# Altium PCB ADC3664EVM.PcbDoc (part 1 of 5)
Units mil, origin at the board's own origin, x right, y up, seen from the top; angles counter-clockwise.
Board outline 3900 x 2716.54 mil, 10 copper layers (Top Layer, L2 GND, L3 PWR, L4 GND, L5 SIG, L6 GND, L7 GND, L8 PWR, L9 GND, Bottom Layer), stack 61.2 mil thick; 332 components, 223 nets, 1425 pads, 969 vias.
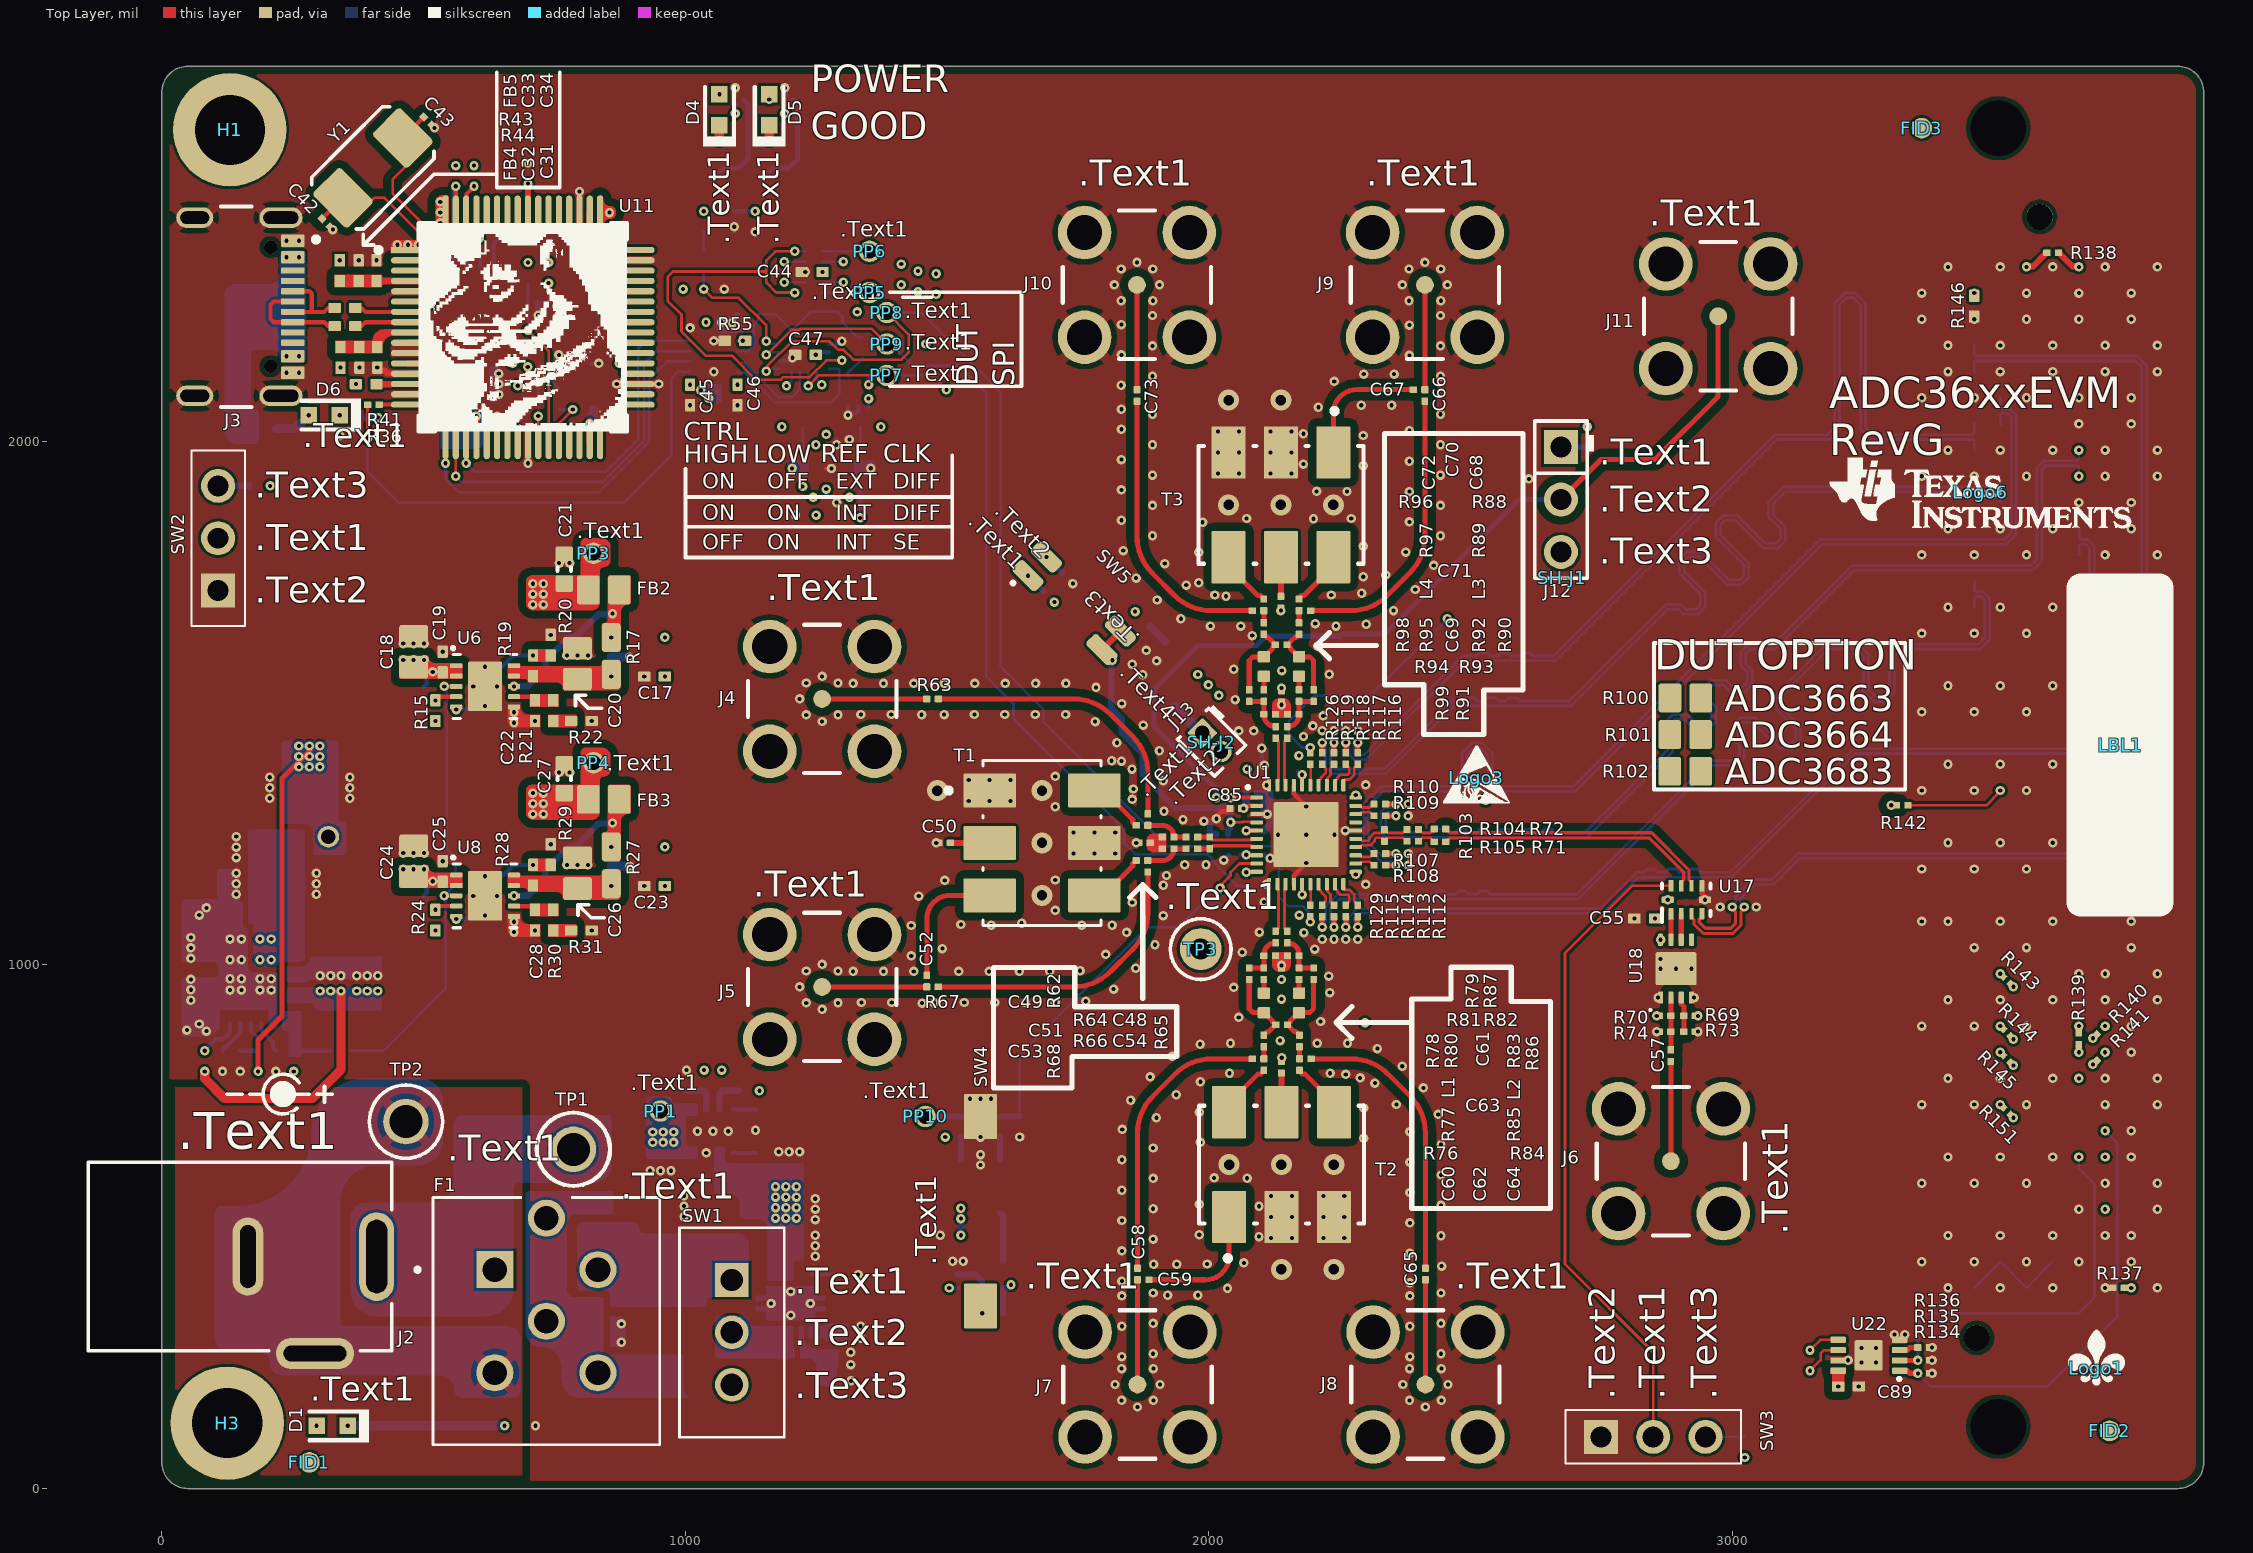
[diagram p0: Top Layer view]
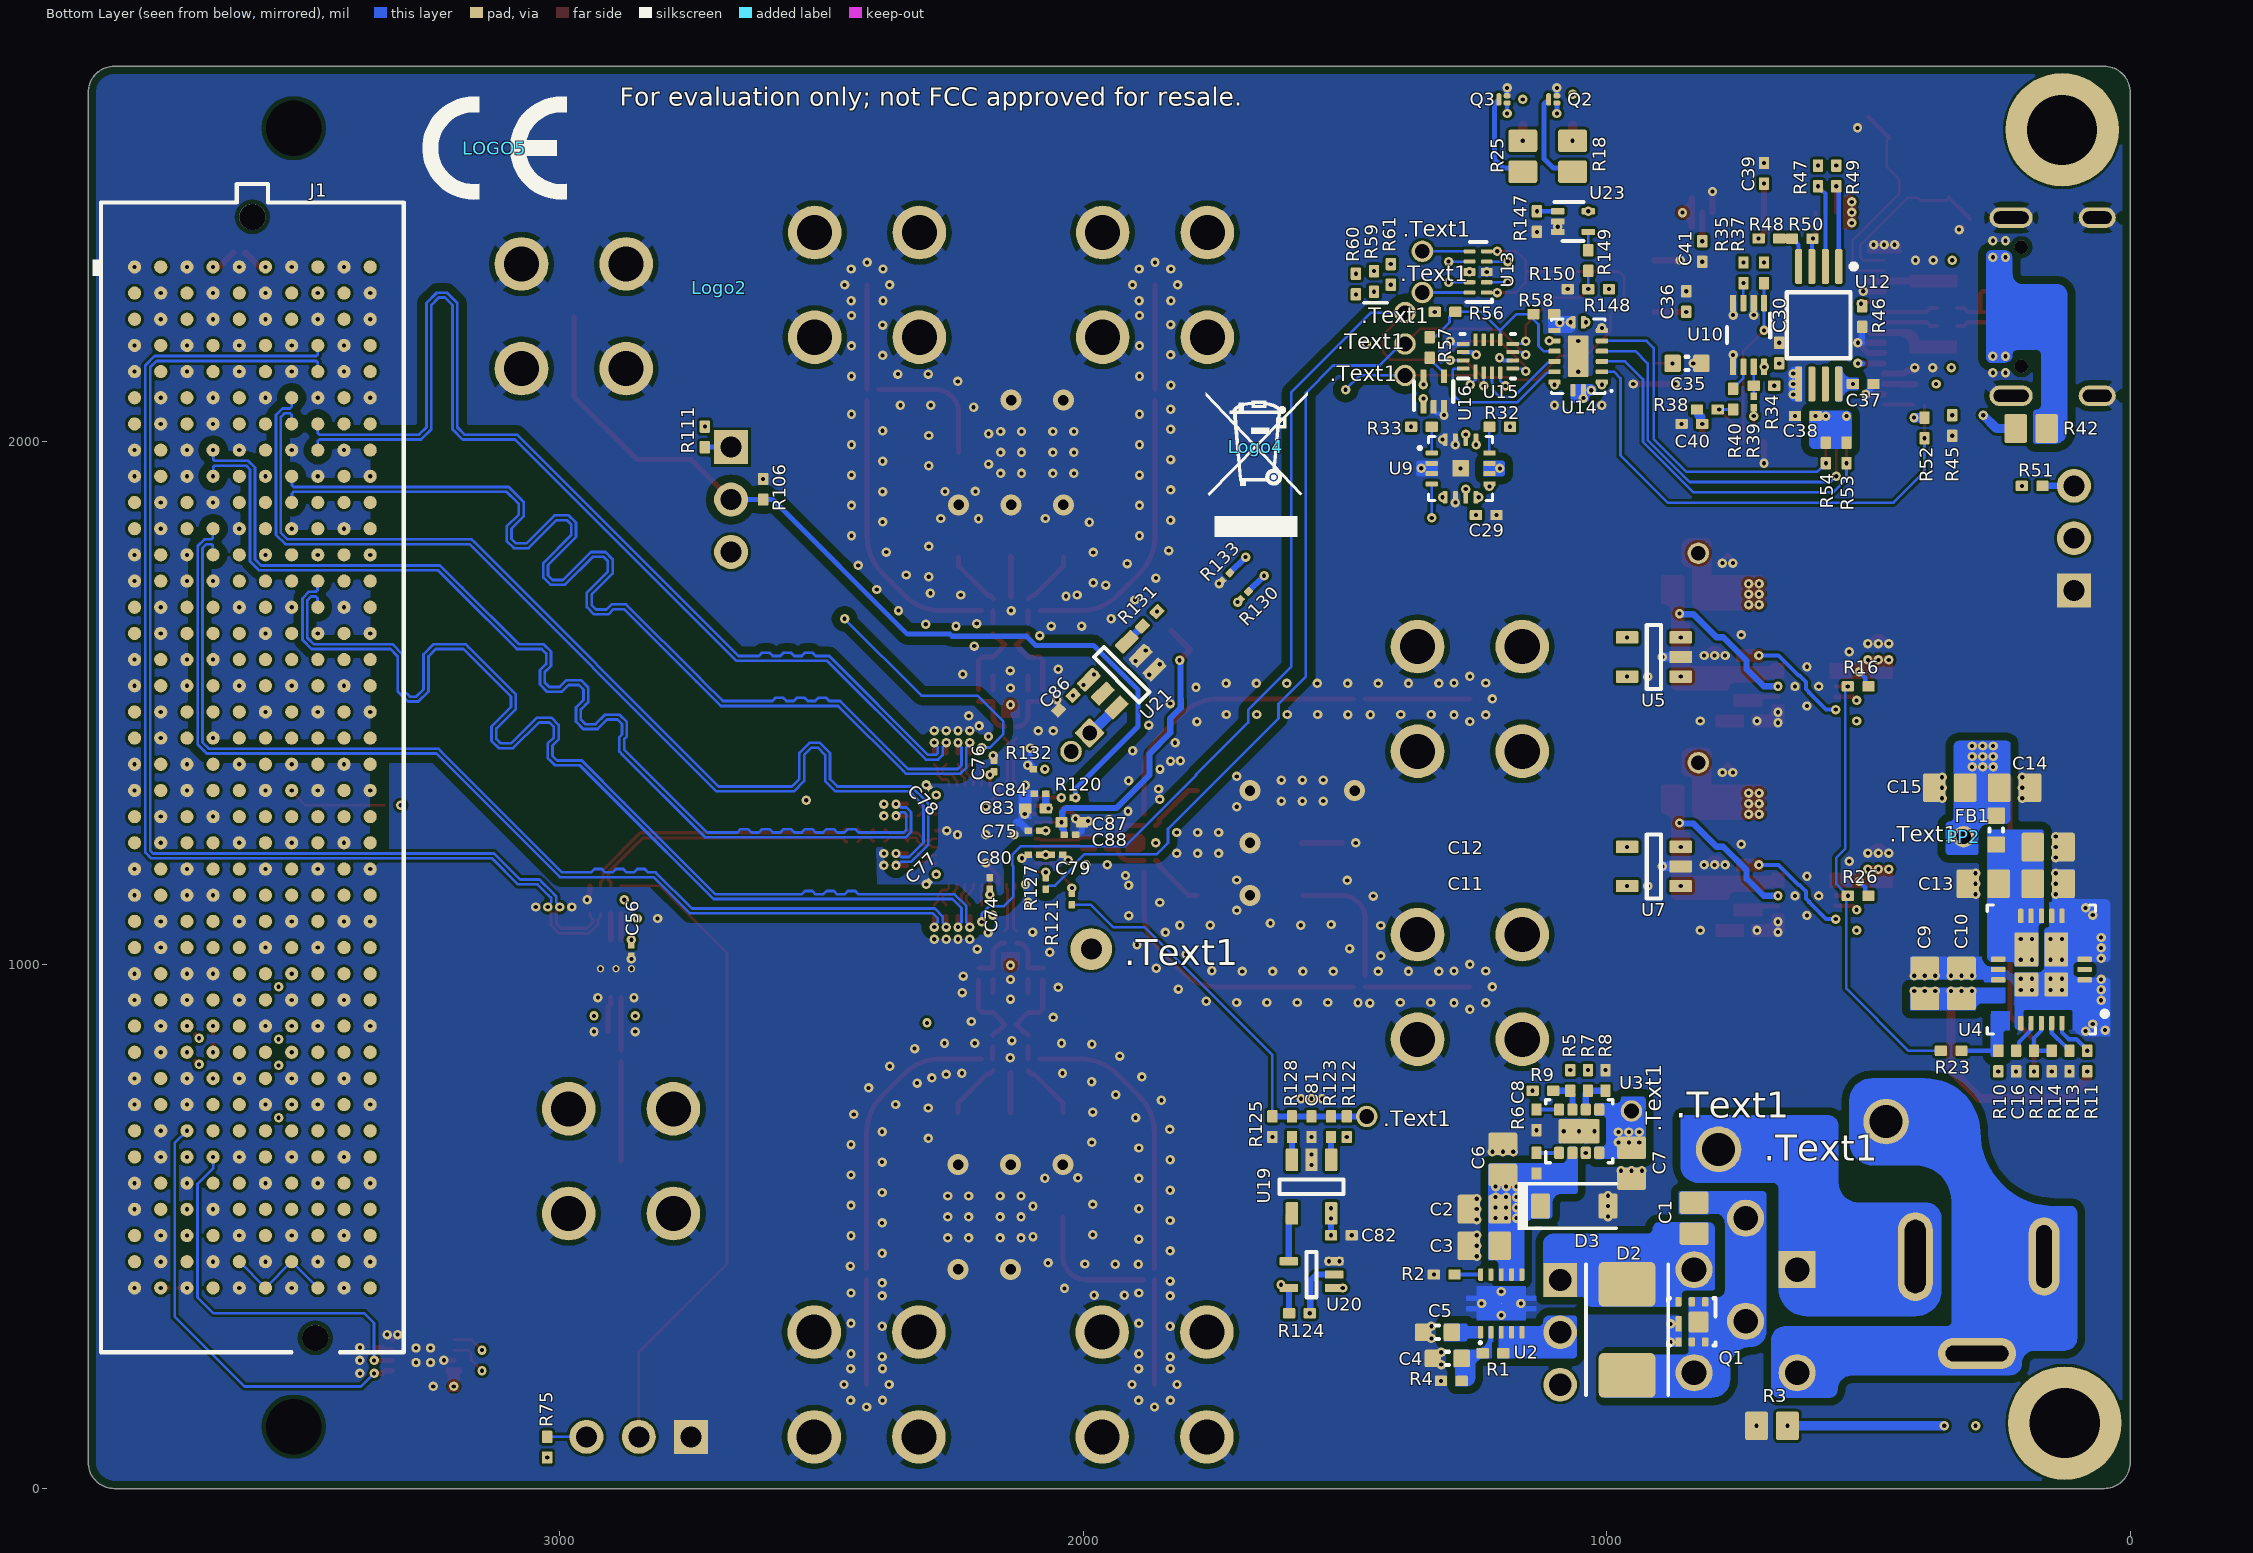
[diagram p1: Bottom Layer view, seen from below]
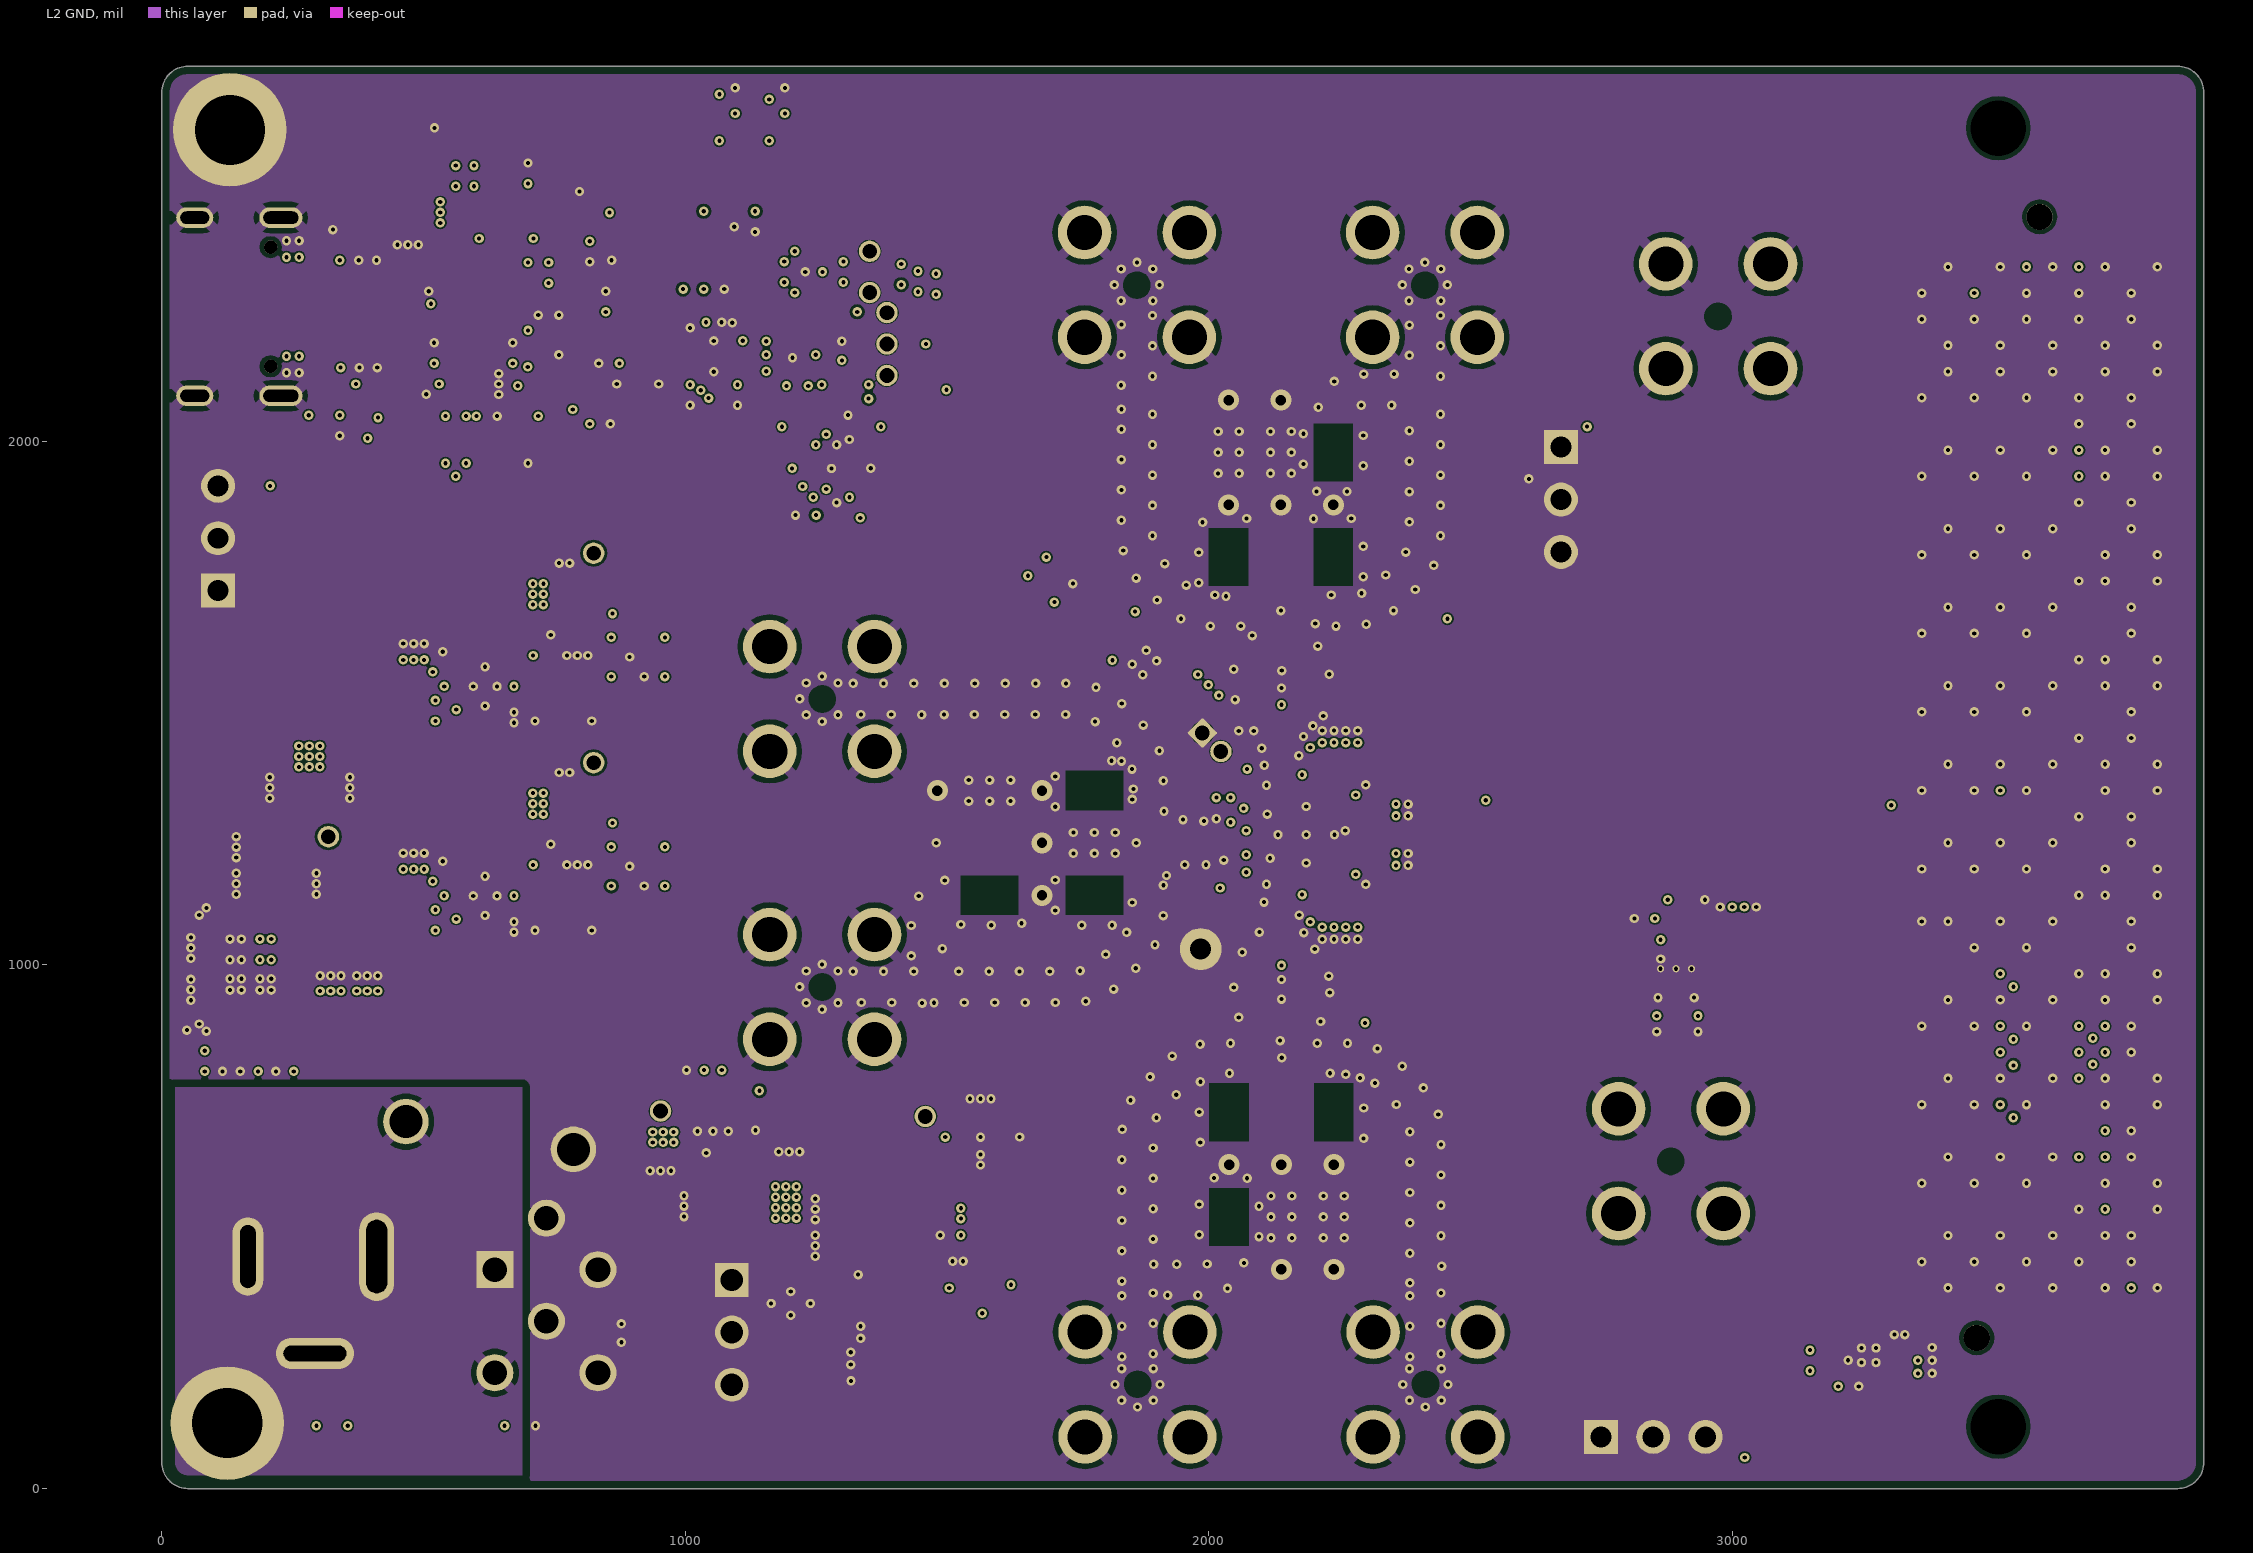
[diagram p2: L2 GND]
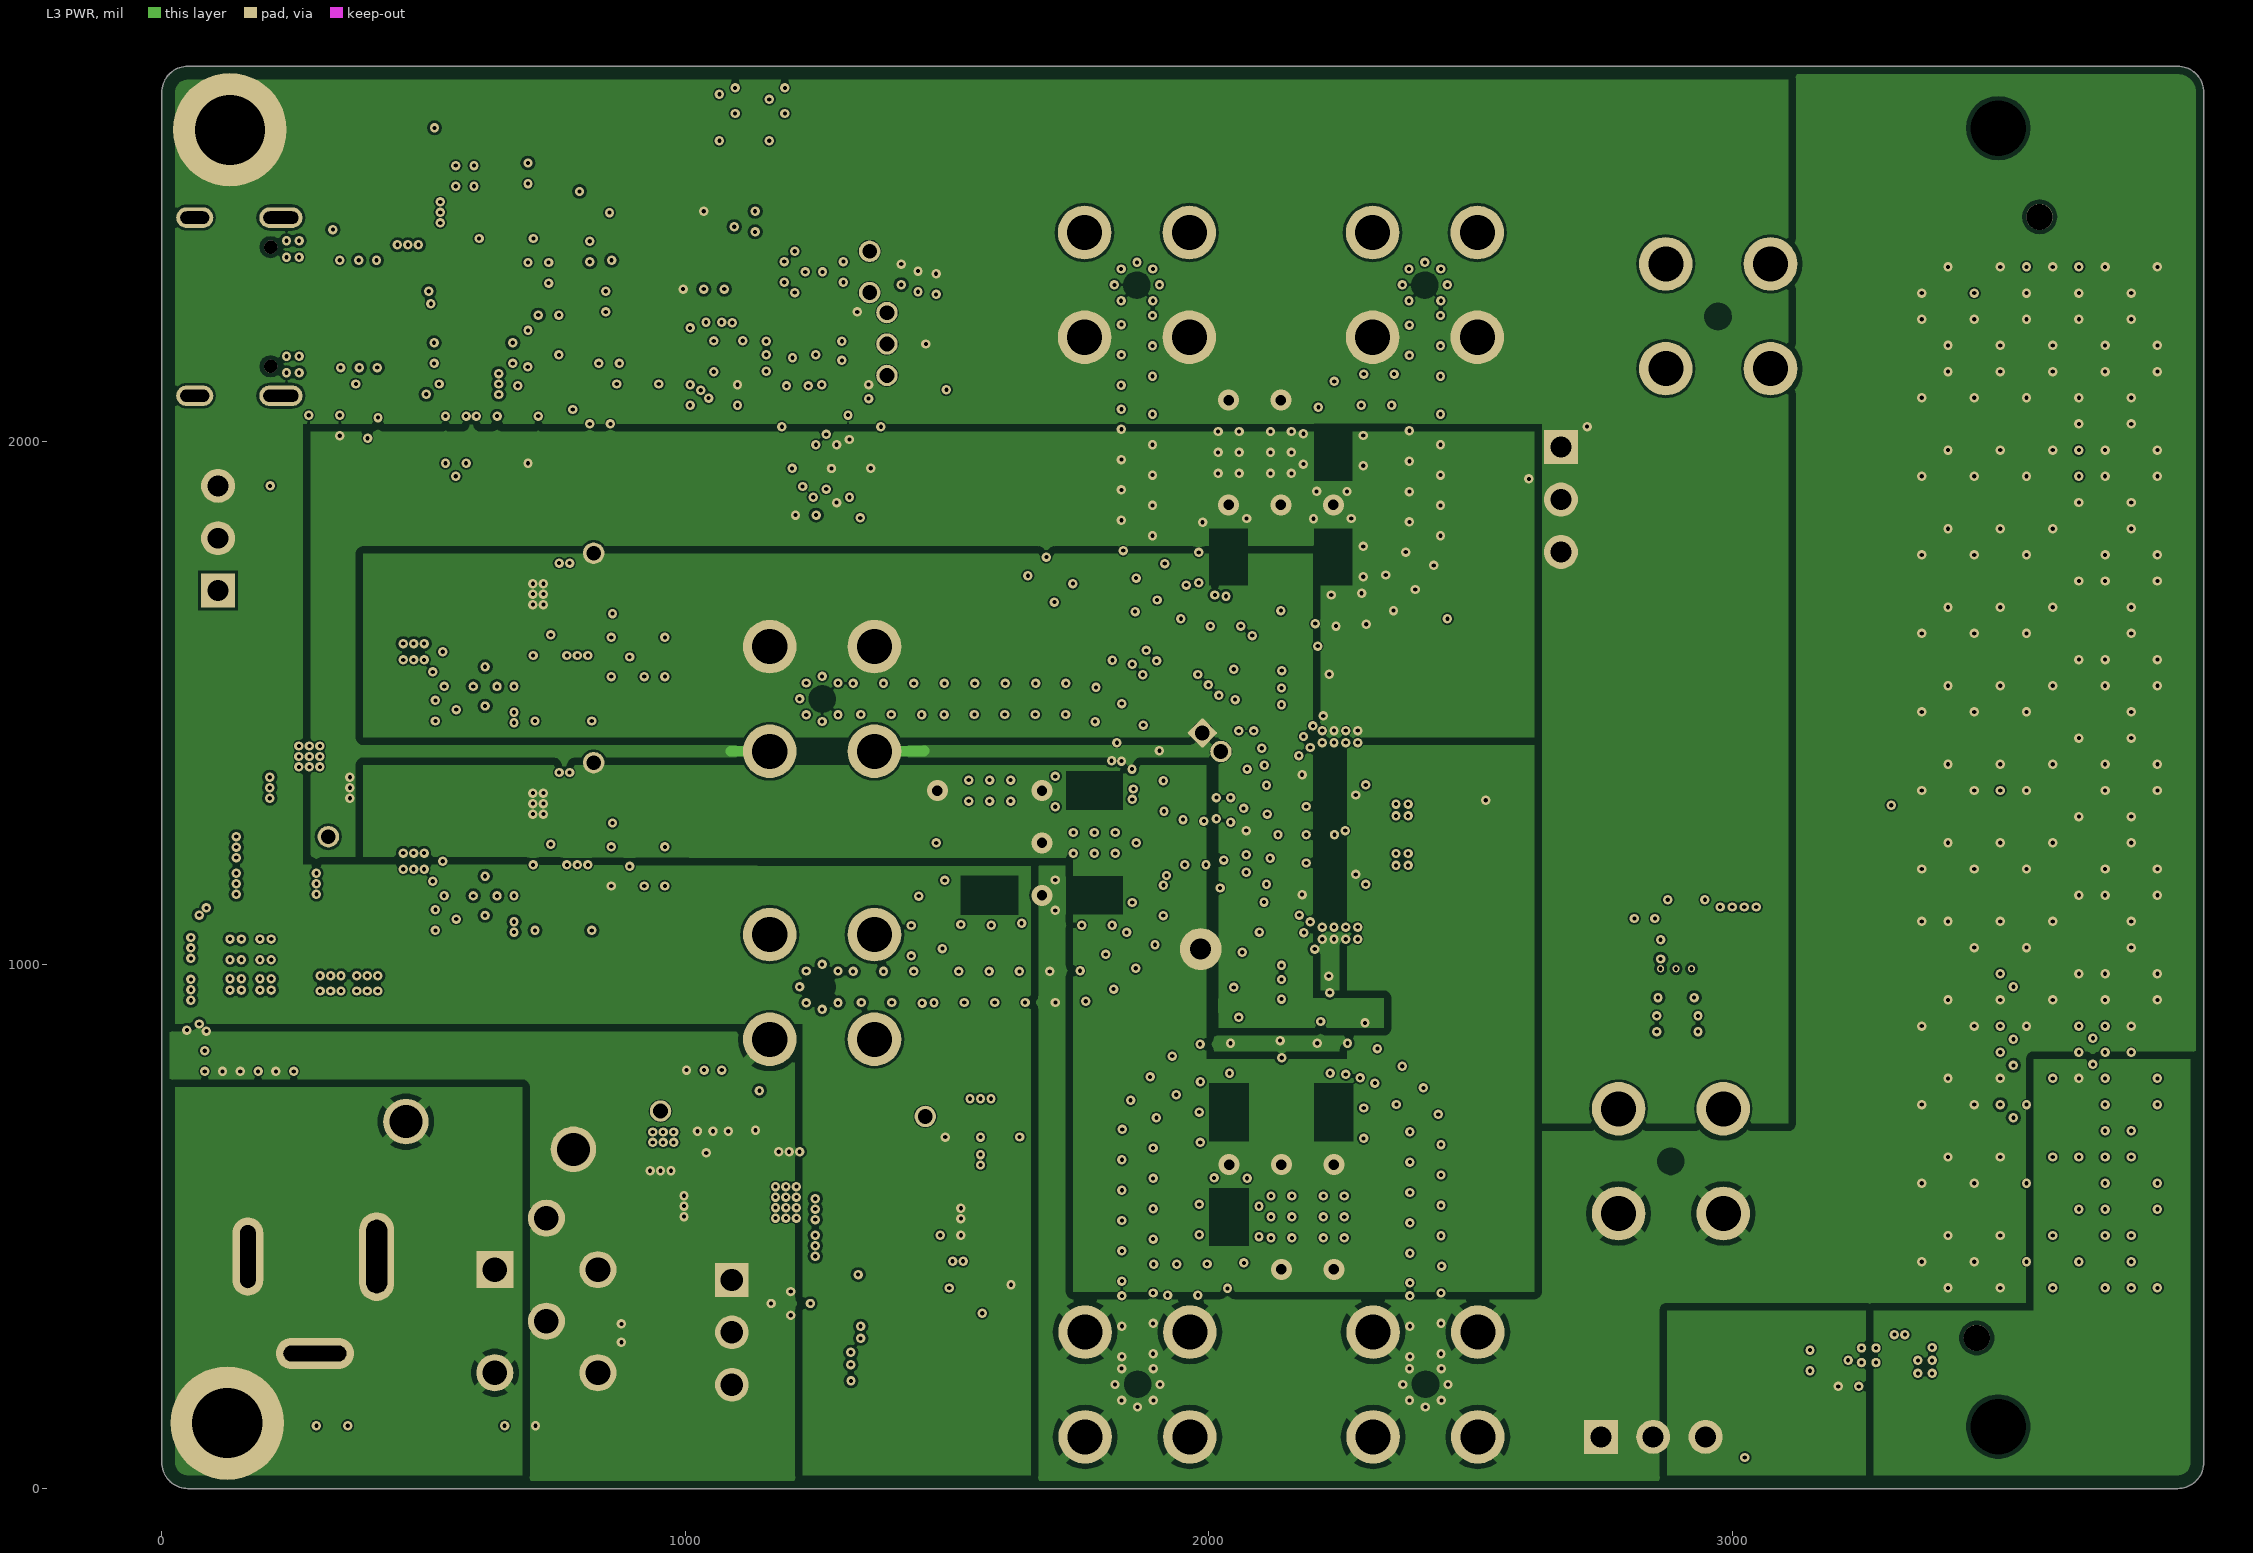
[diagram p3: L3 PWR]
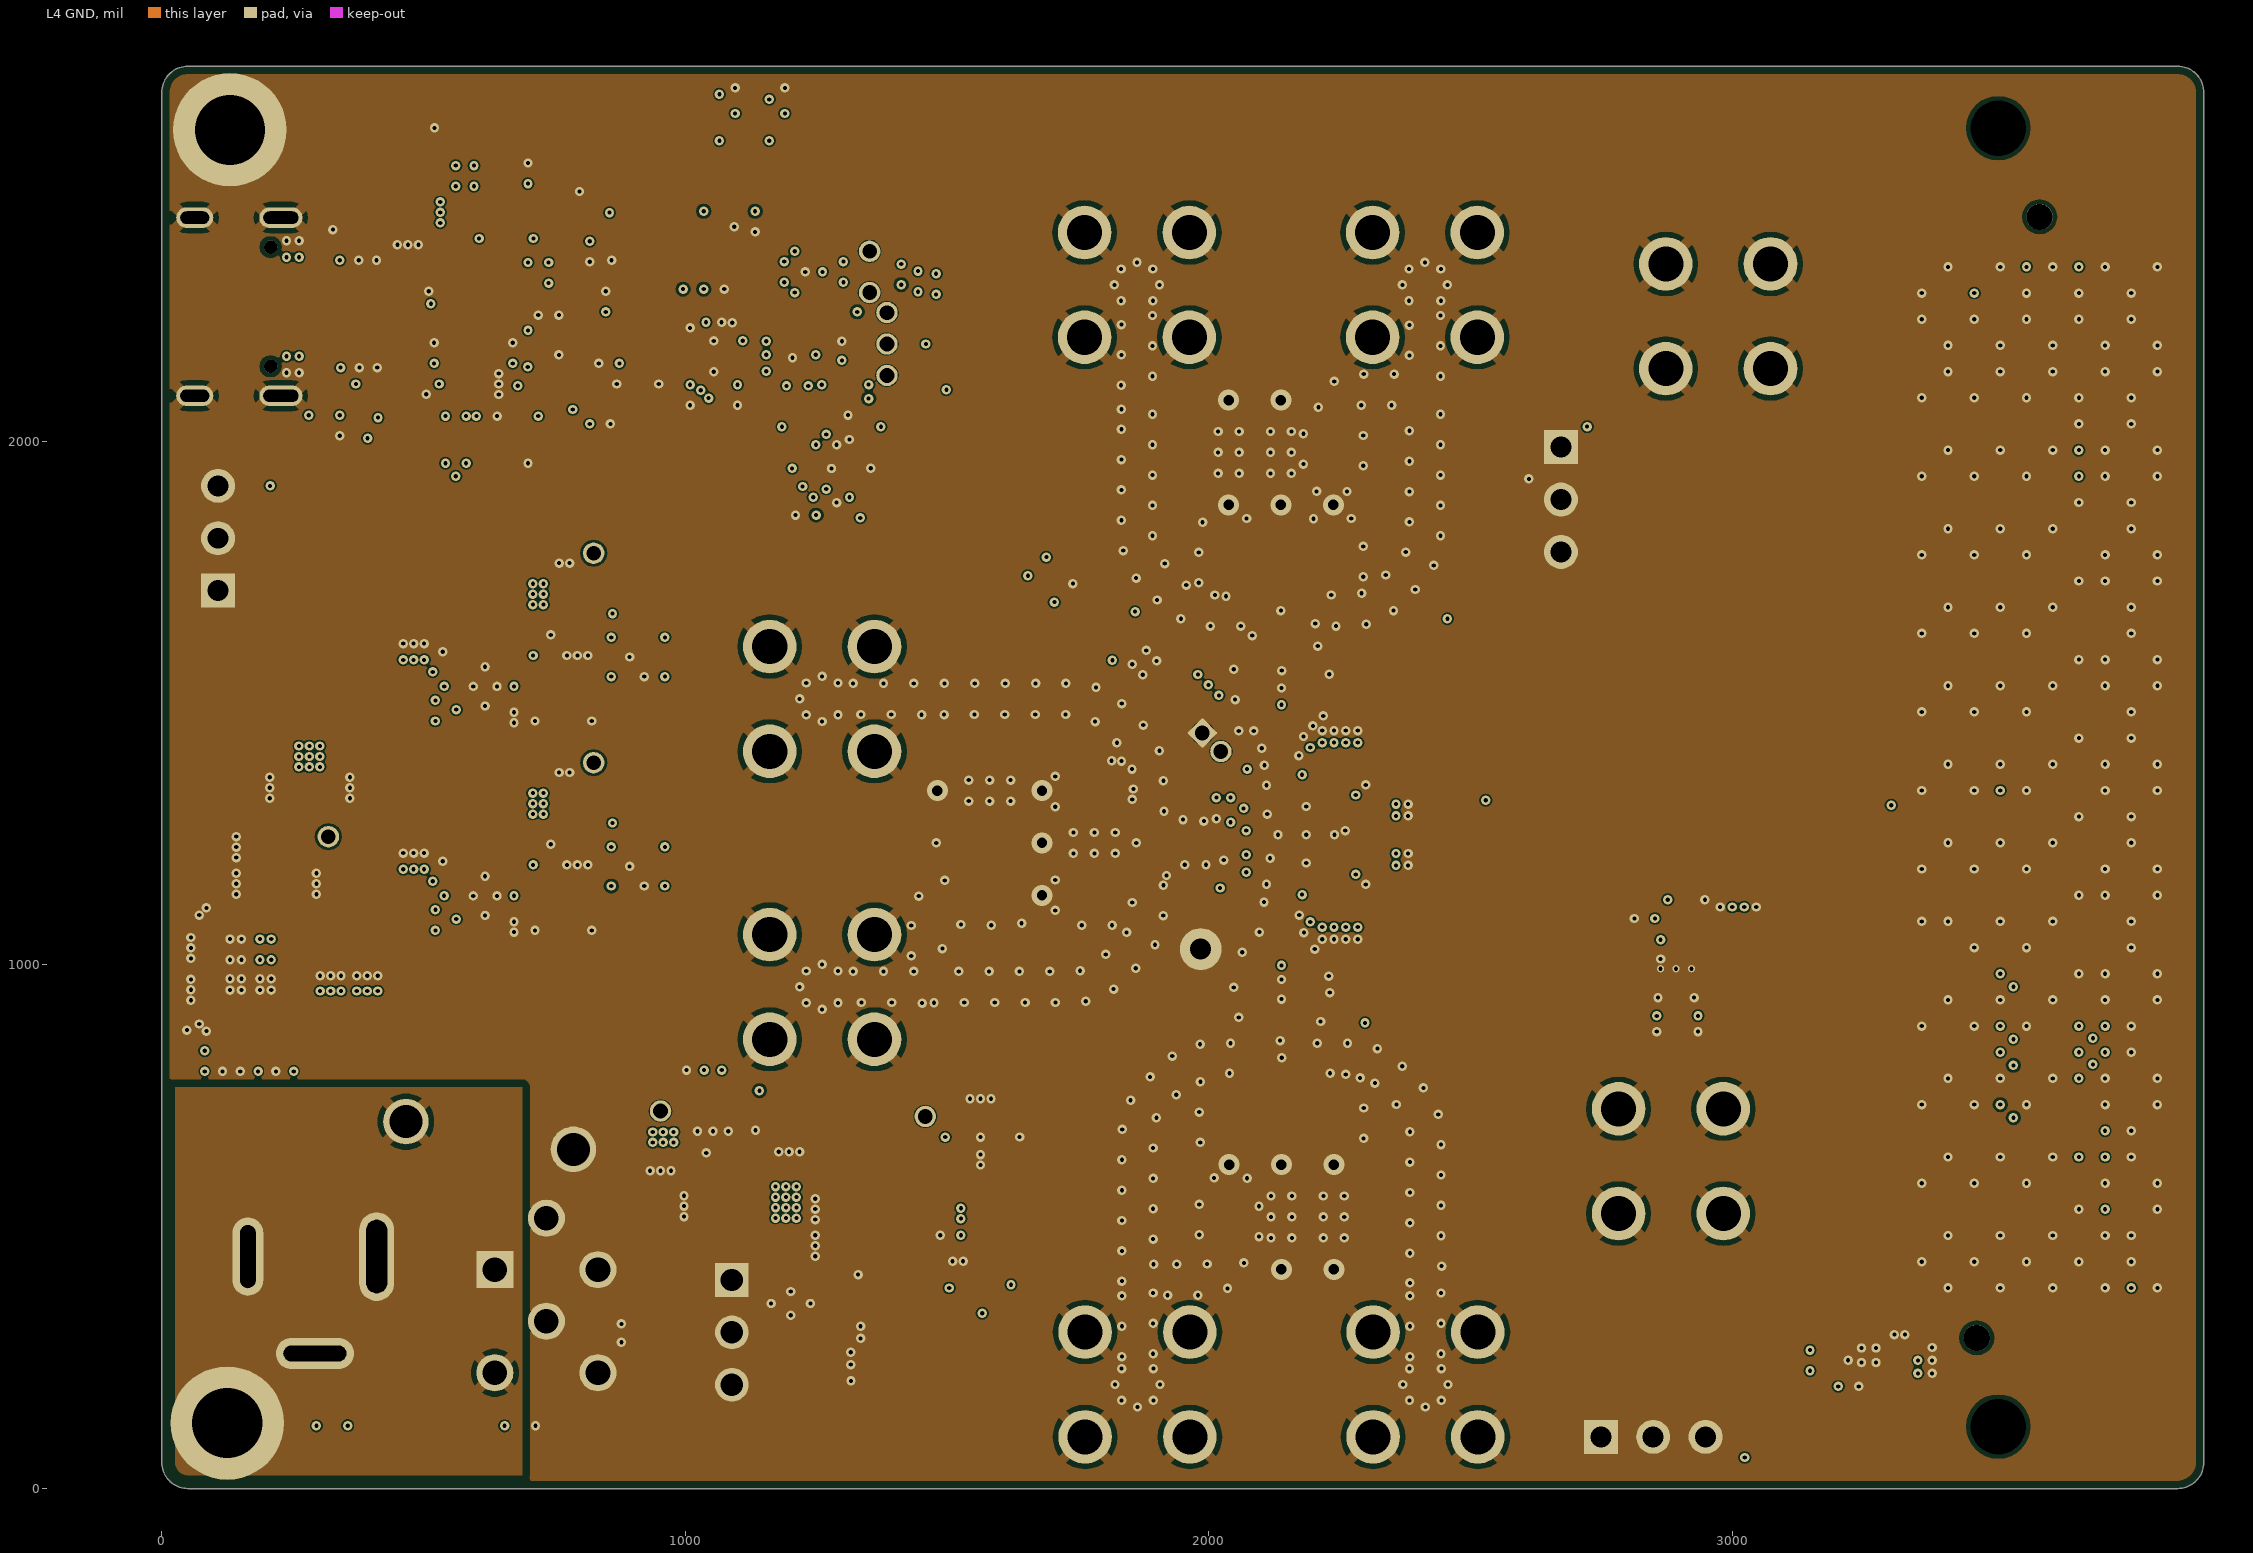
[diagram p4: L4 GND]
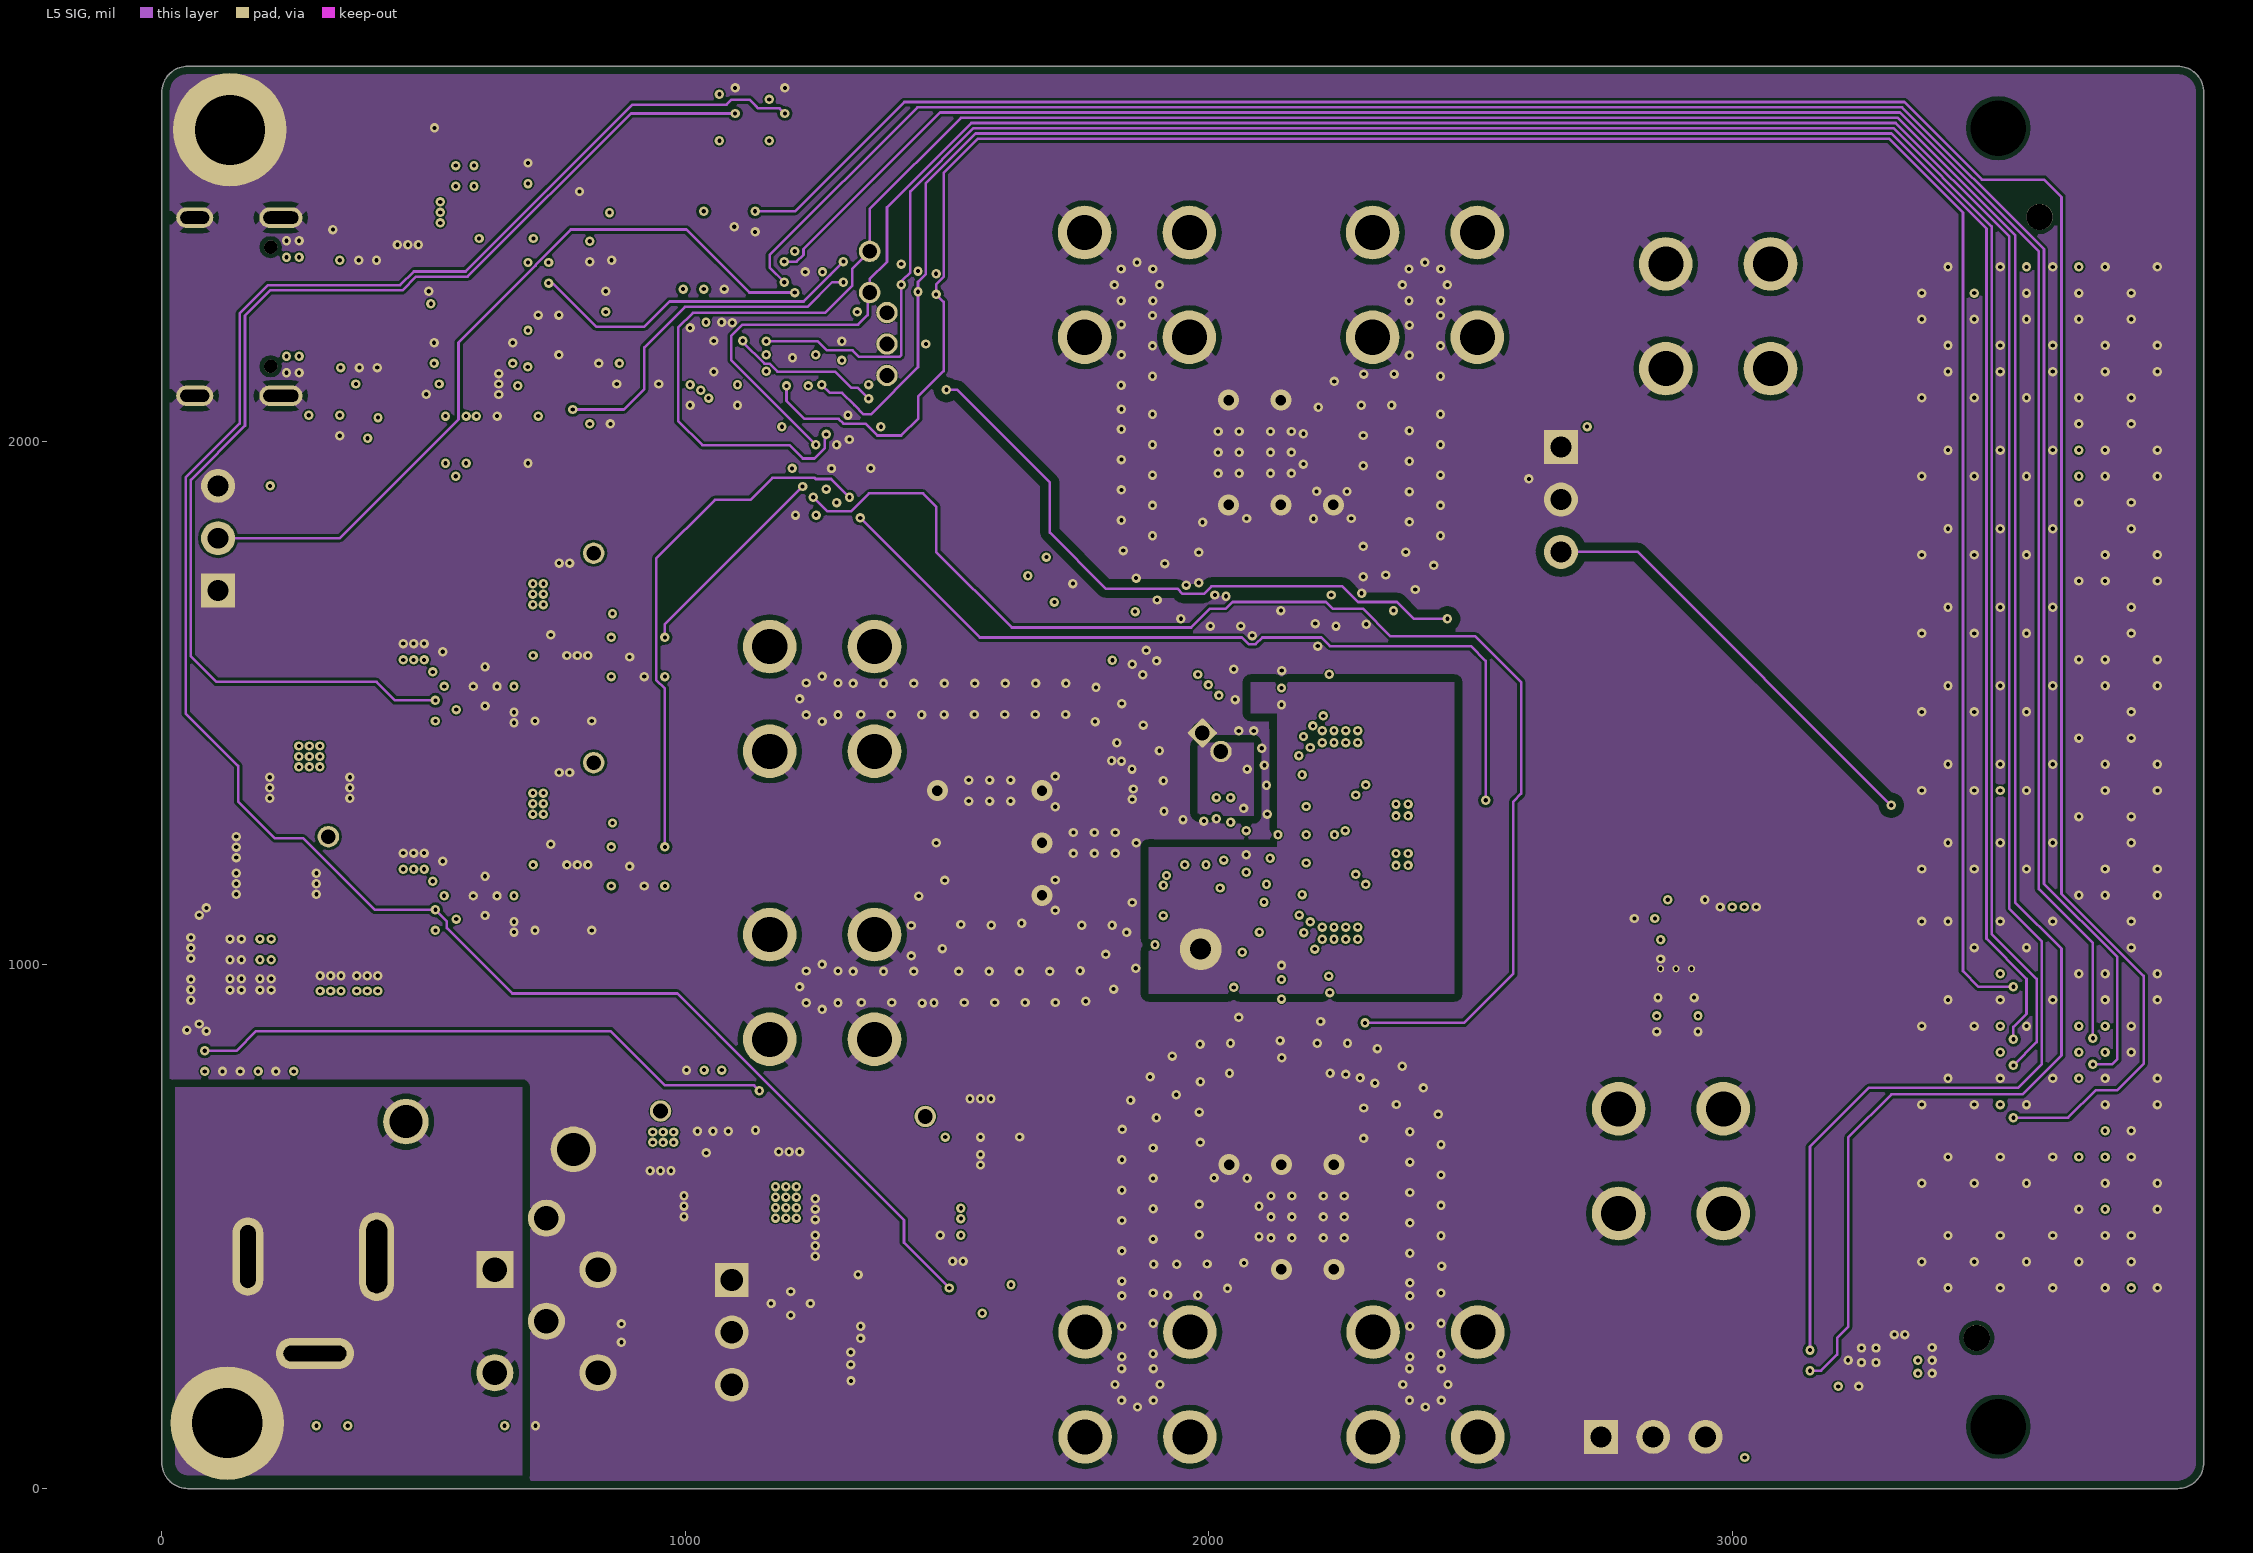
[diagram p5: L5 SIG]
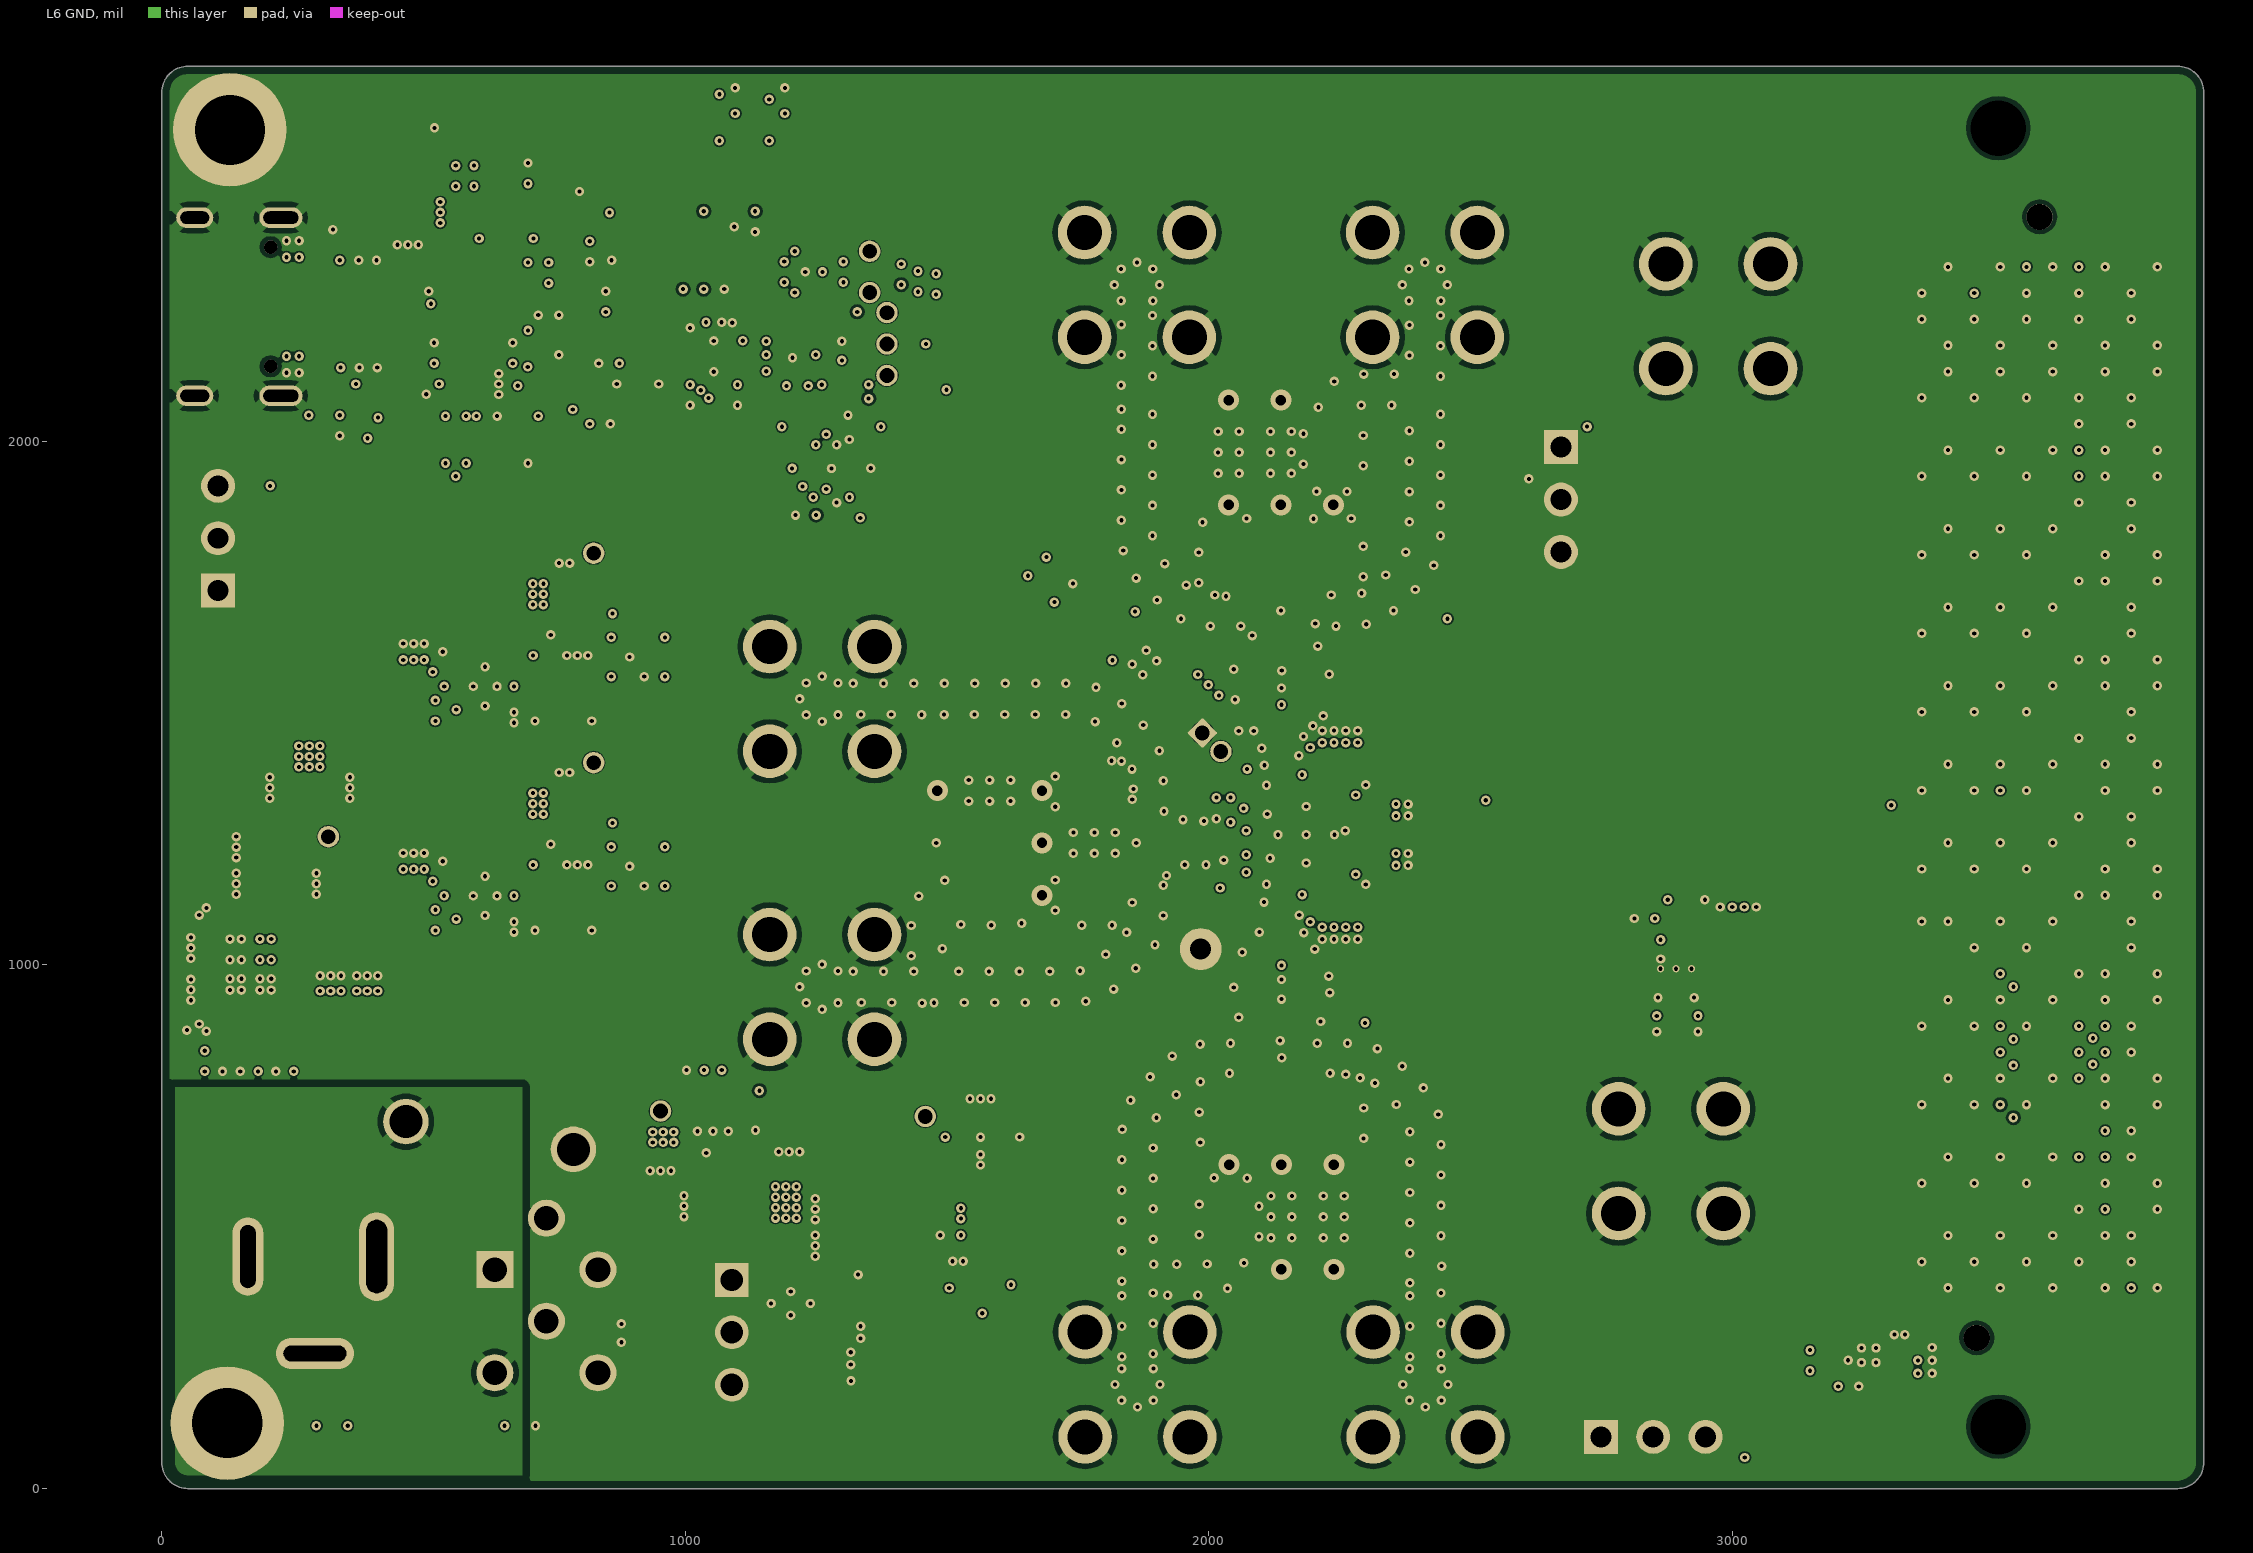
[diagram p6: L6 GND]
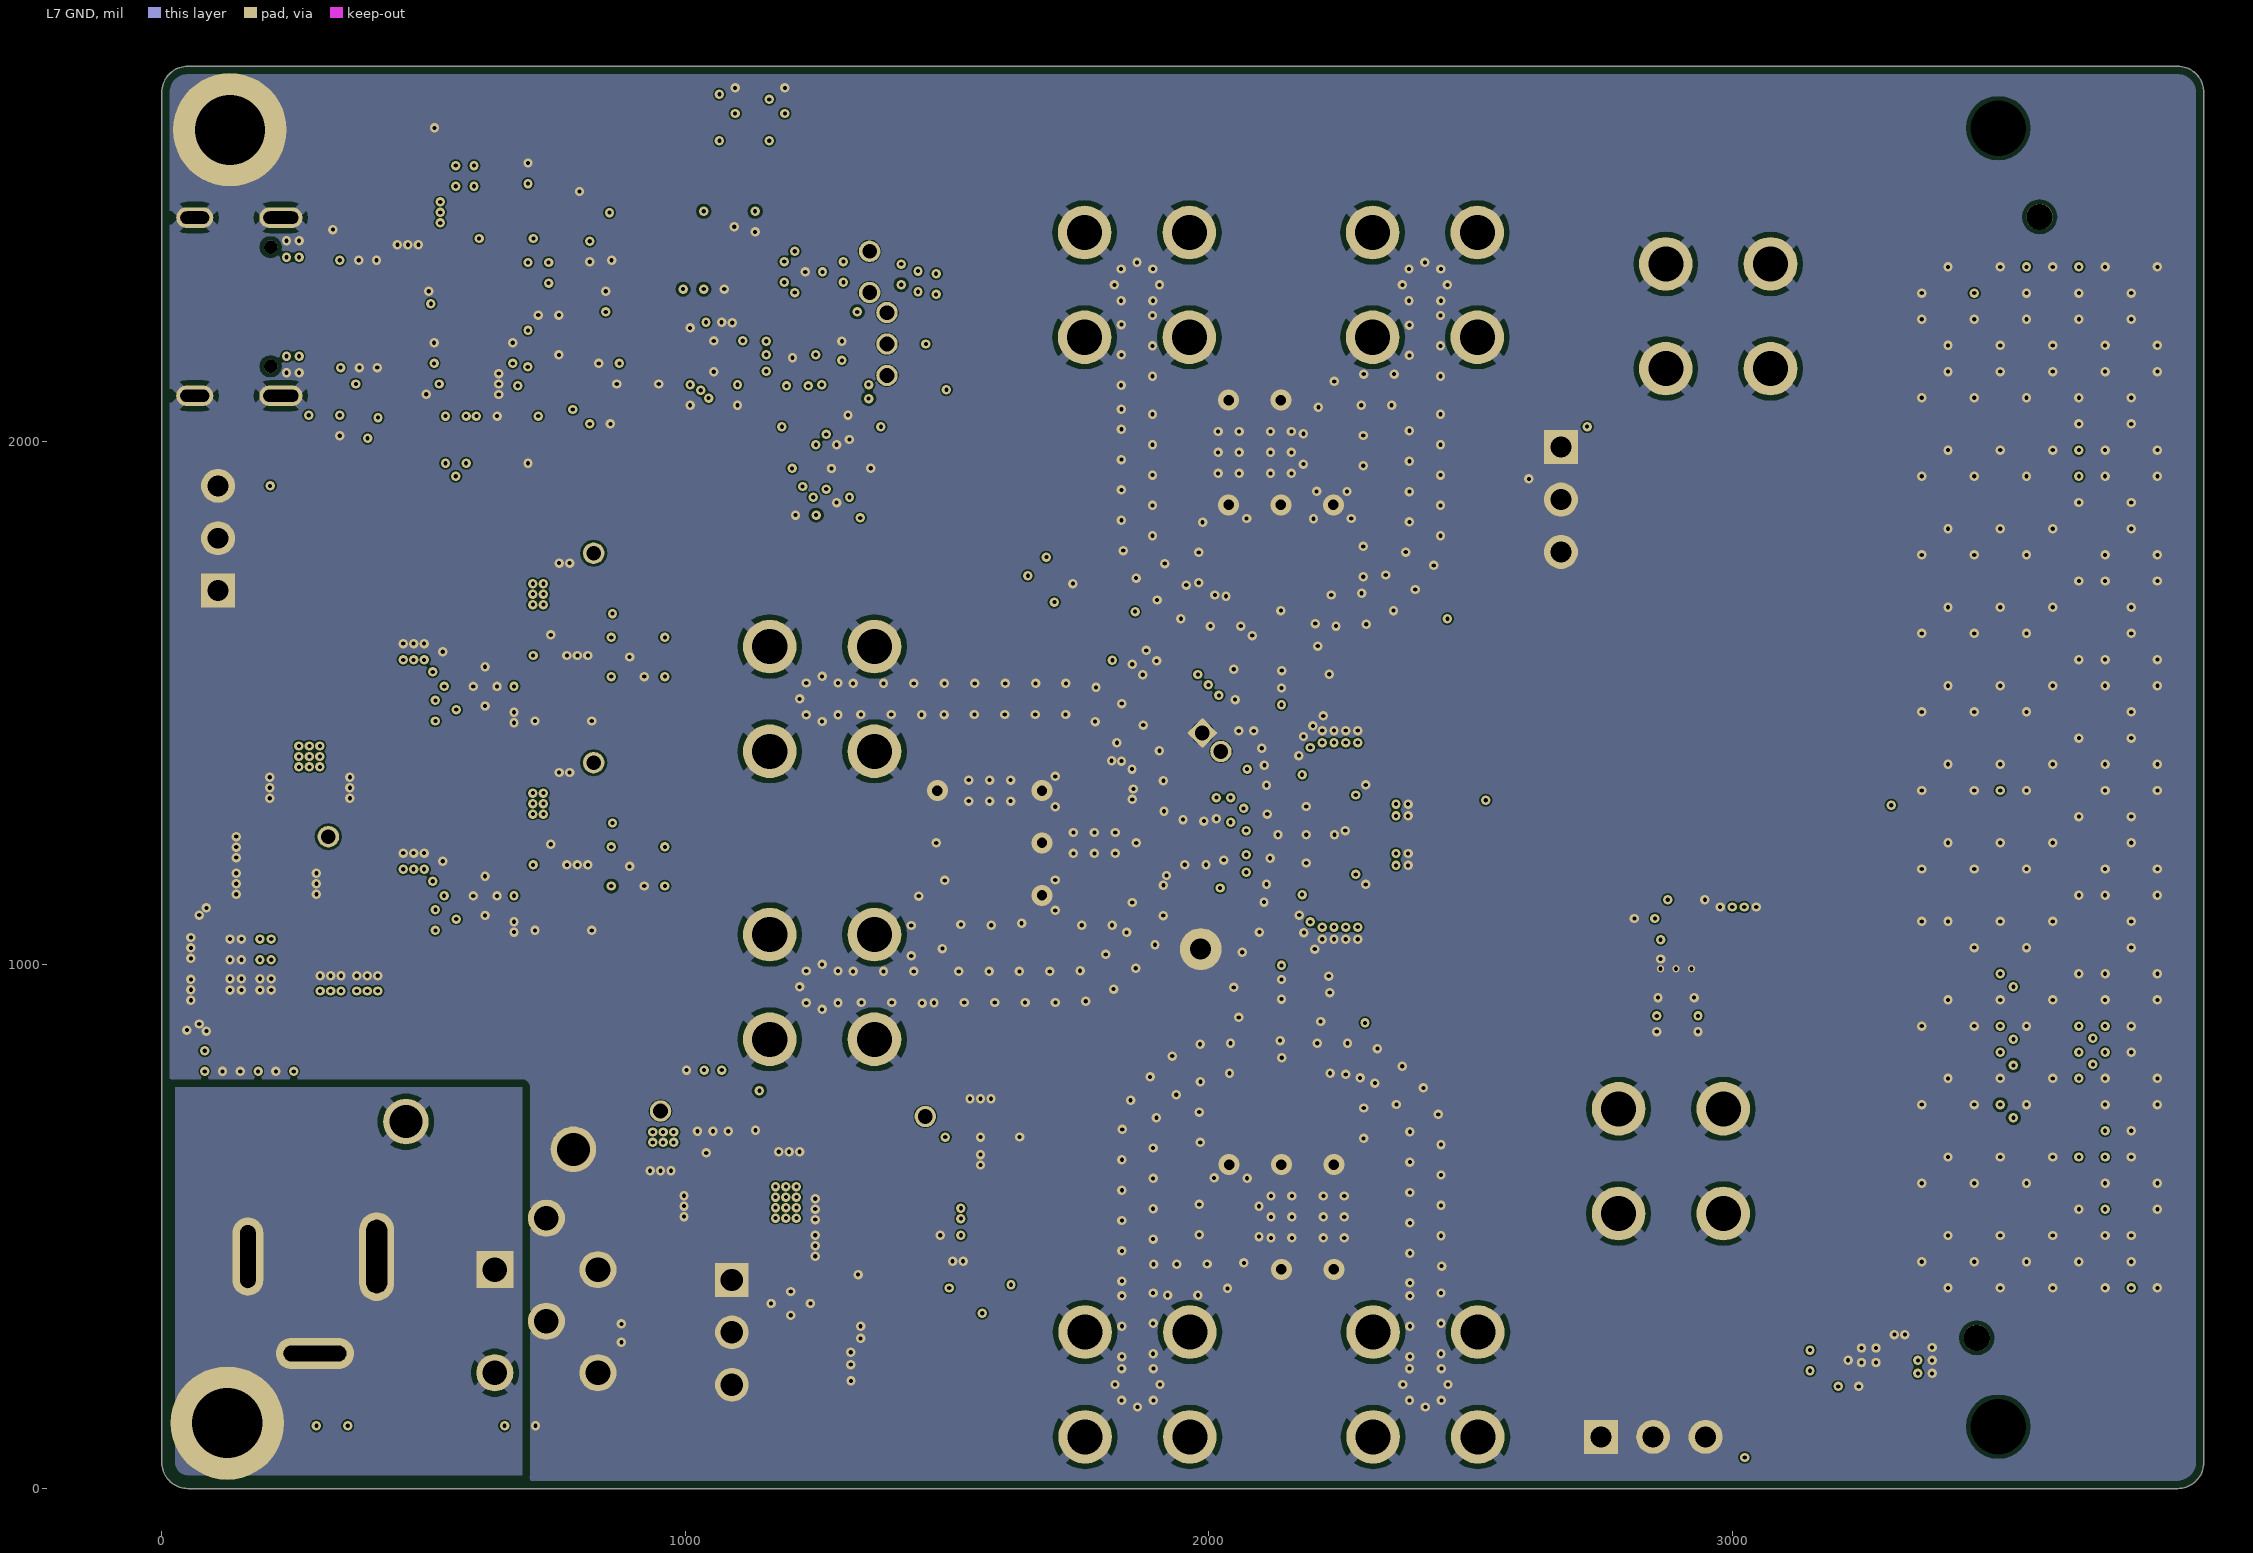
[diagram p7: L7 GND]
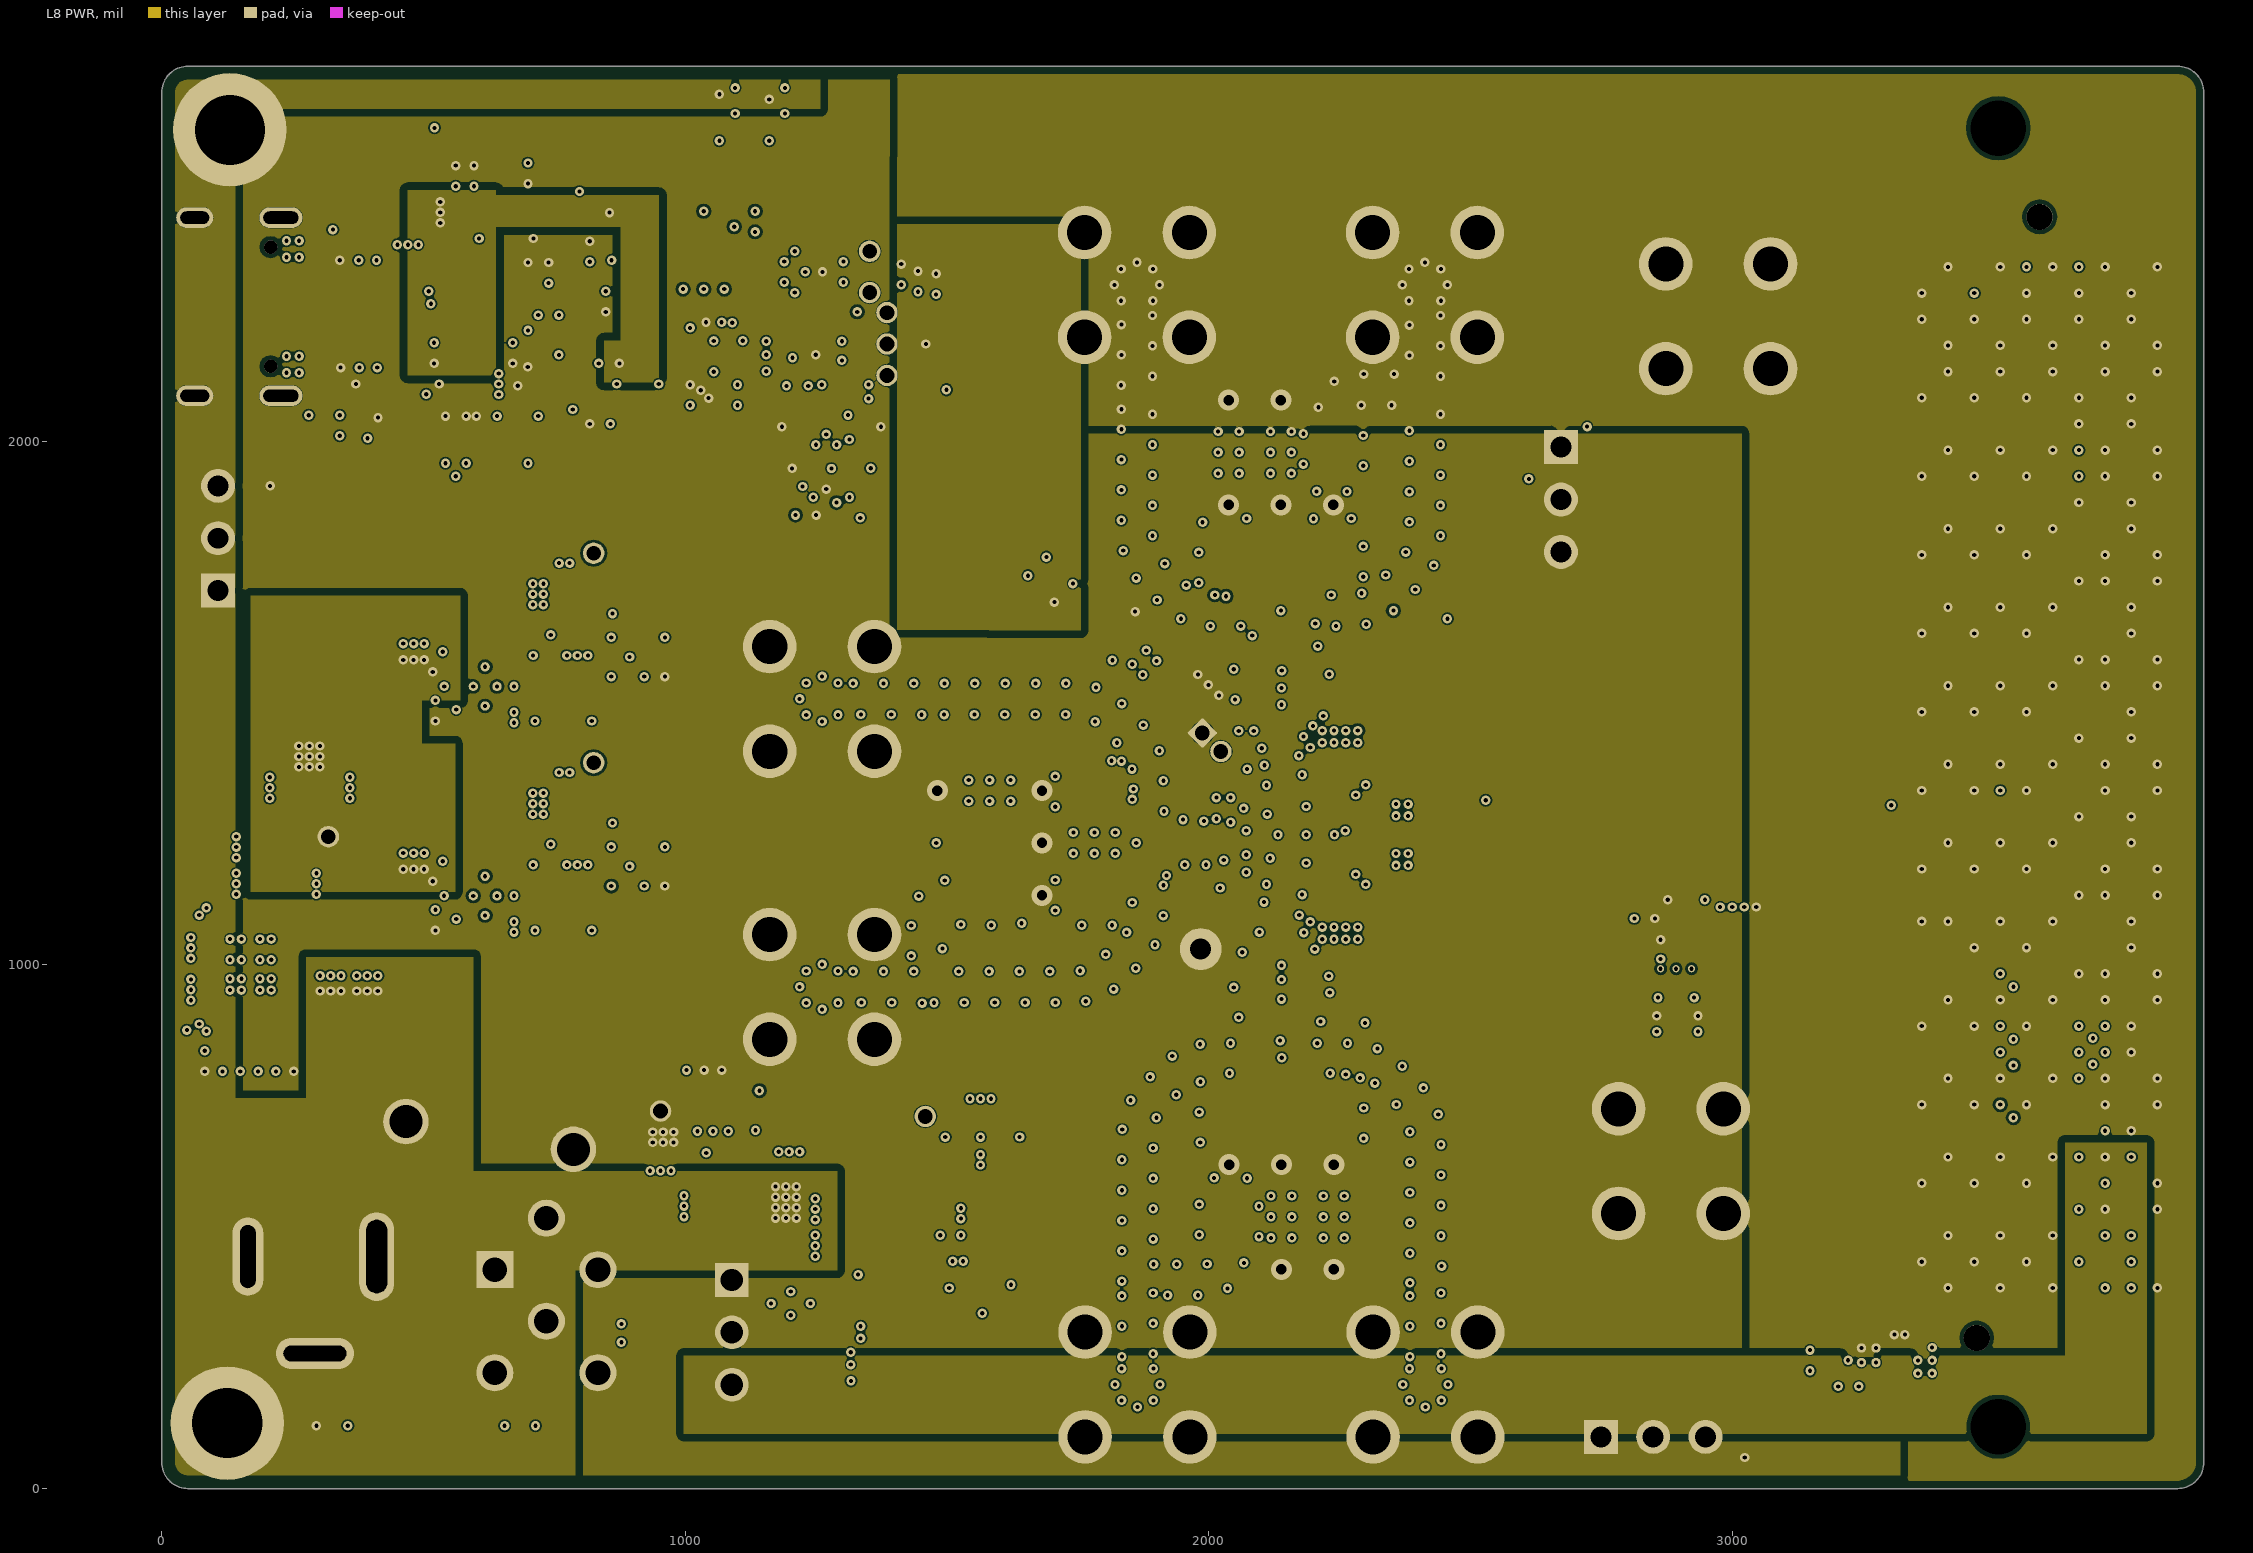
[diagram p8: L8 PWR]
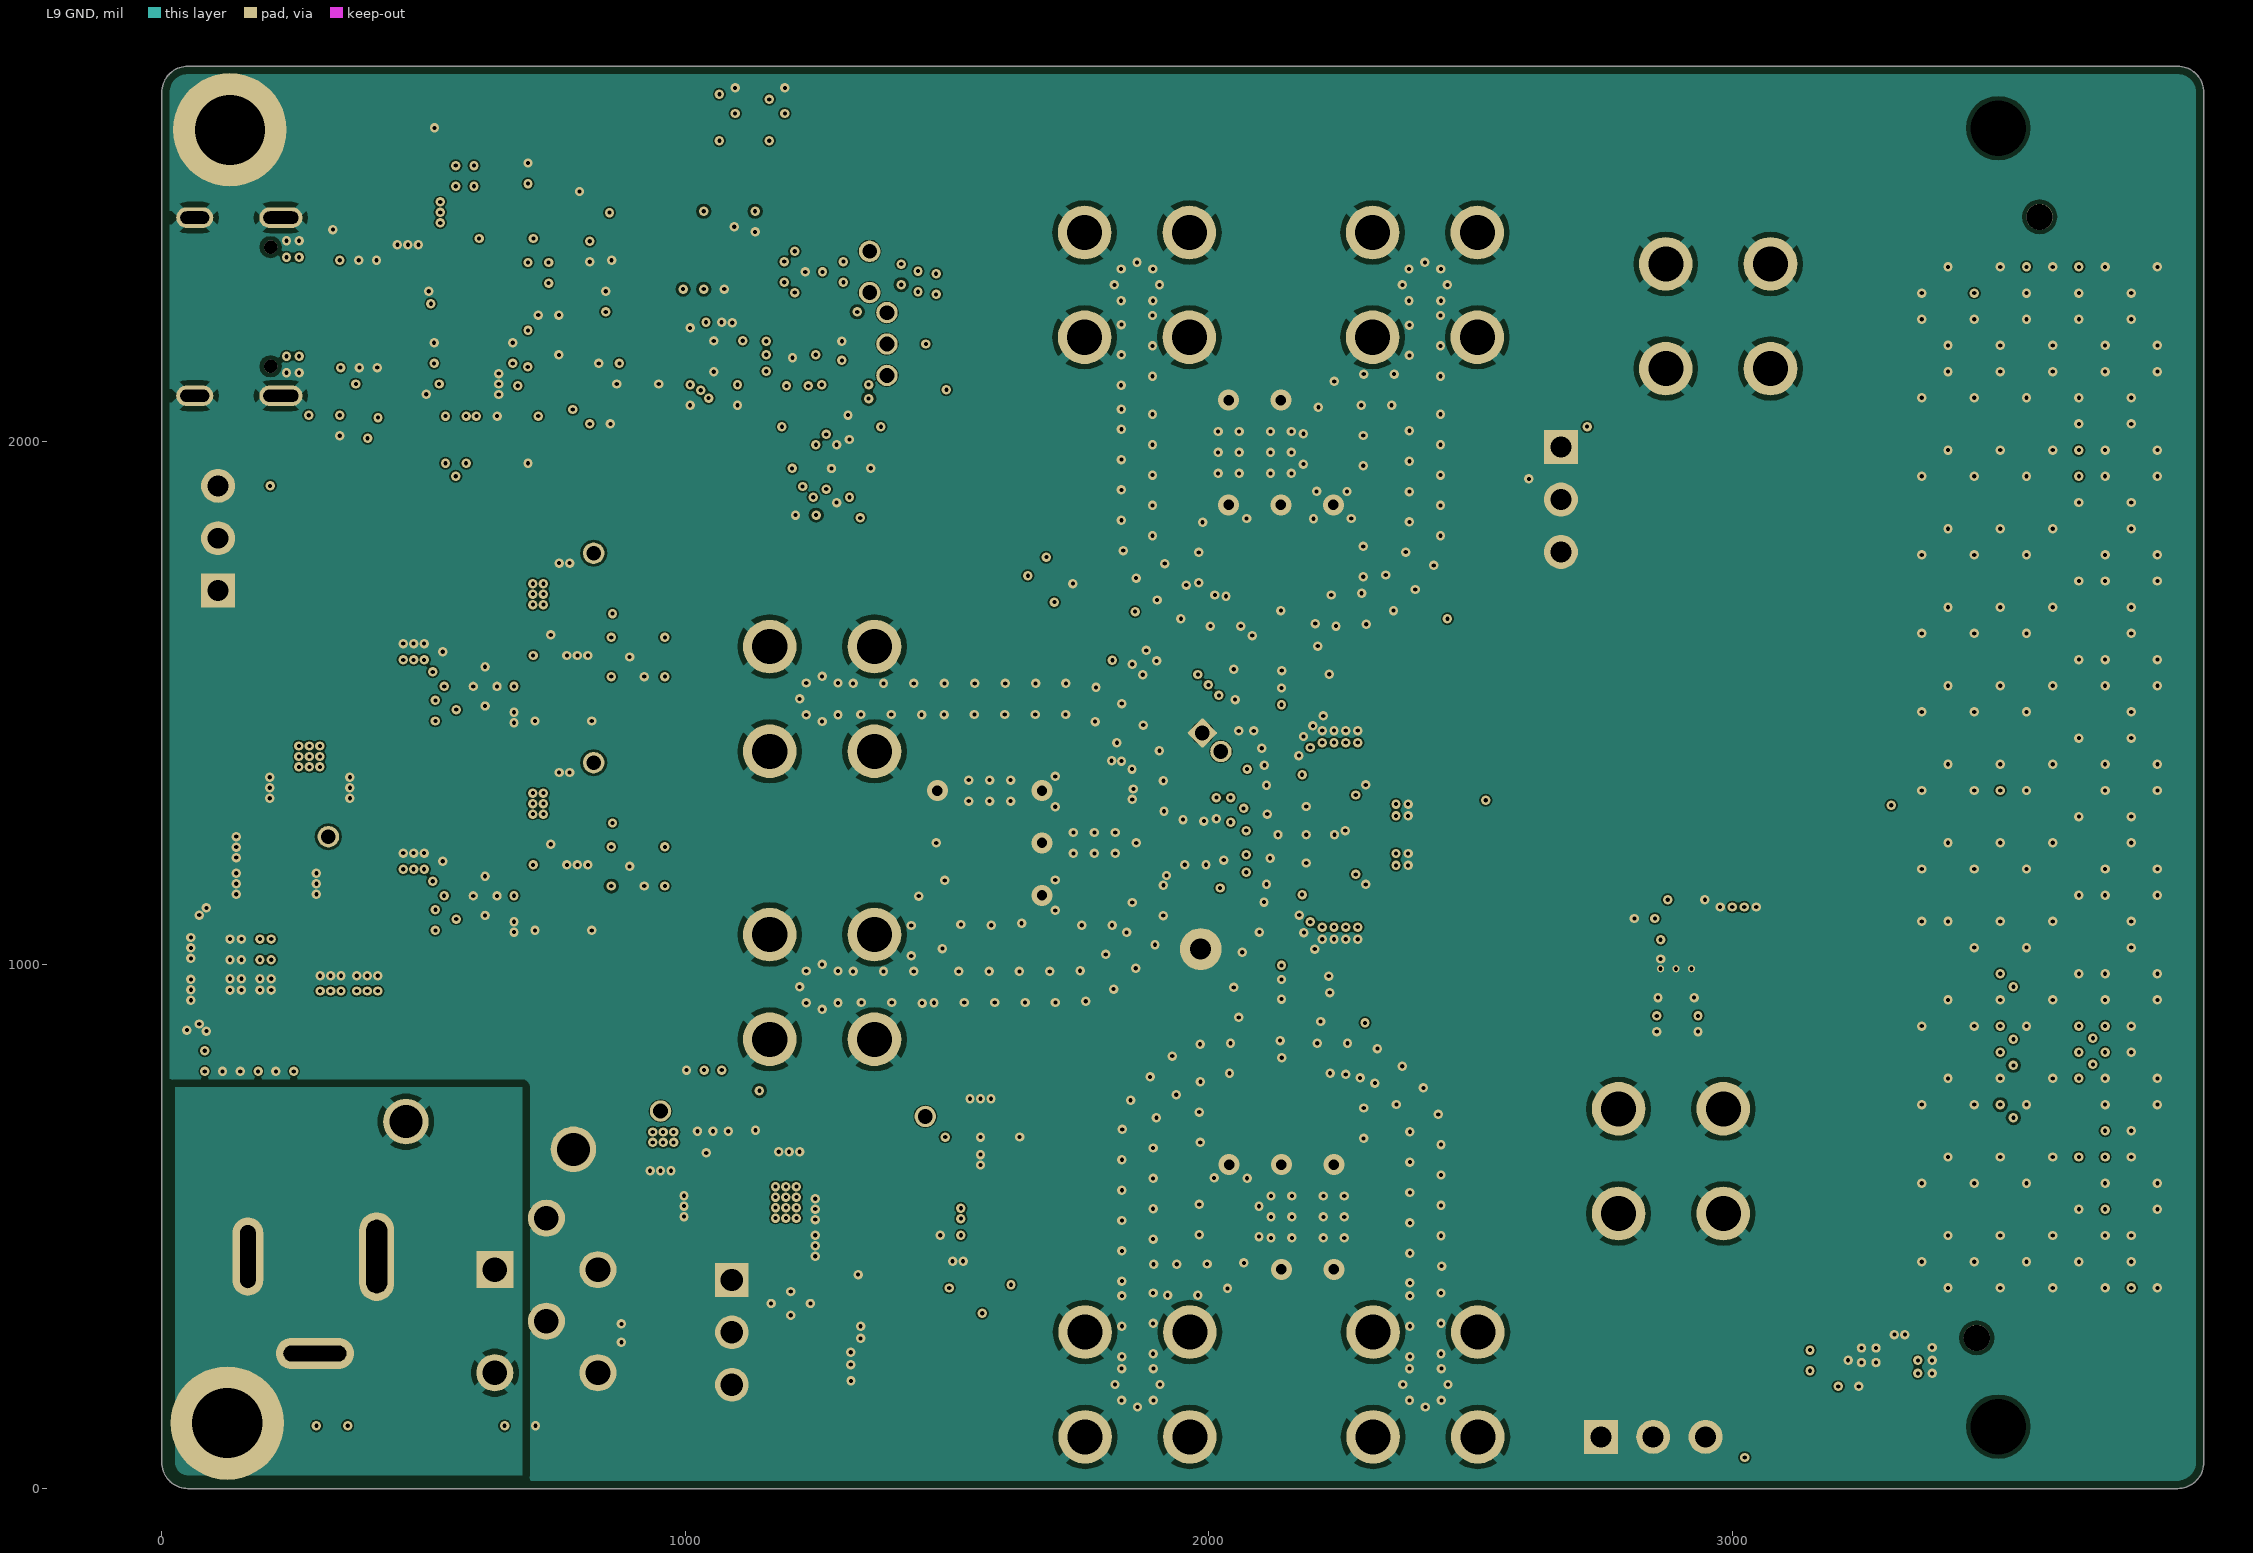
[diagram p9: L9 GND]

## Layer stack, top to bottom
Top Solder: solder mask 0.4, Solder Resist, Dk 3.5
Top Layer: signal copper 1.4
Dielectric 1: core 5, FR408HR, Dk 3.62
L2 GND: signal copper 1.4
Dielectric 3: prepreg 3.2, FR408HR, Dk 3.46
L3 PWR: signal copper 1.4
Dielectric 5: core 3, FR408HR, Dk 3.6
L4 GND: signal copper 1.4
Dielectric 7: prepreg 9.2, FR408HR, Dk 3.68
L5 SIG: signal copper 1.4
Dielectric1: prepreg 6.4, FR408HR, Dk 3.46
L6 GND: signal copper 1.4
Dielectric 8: prepreg 9.2, FR408HR, Dk 3.68
L7 GND: signal copper 1.4
Dielectric 6: core 3, FR408HR, Dk 3.6
L8 PWR: signal copper 1.4
Dielectric 4: prepreg 3.2, FR408HR, Dk 3.46
L9 GND: signal copper 1.4
Dielectric 2: core 5, FR408HR, Dk 3.62
Bottom Layer: signal copper 1.4
Bottom Solder: solder mask 0.4, Solder Resist, Dk 3.5

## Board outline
0,100 0,2666.54 cw(c50,2666.54) 50,2716.54 3850,2716.54 cw(c3850,2666.54) 3900,2666.54 3900,50 cw(c3850,50) 3850,0 50,0 cw(c50,50) 0,50

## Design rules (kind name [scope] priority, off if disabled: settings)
AcuteAngle [All] p1: minimum=4.50000000000000E+0001 checktracksonly=TRUE
AssemblyTestPointUsage [All] p1: valid=2
BoardOutlineClearance BoardOutlineClearance_Poly_LY2_GND [OnCopper and IsPoly and InNet('GND') and OnLayer('L2 GND')] p1 off: gap=25 ignorepadtopadclearanceinfootprint=FALSE except(0: Poly-OutlineEdge)
BoardOutlineClearance BoardOutlineClearance_Poly_GND [OnCopper and IsPoly and InNet('GND')] p2: gap=15 ignorepadtopadclearanceinfootprint=FALSE // for poly ground to edge on layer 2 and less pullback on other layers
BoardOutlineClearance BoardOutlineClearance_MountingHoles [OnCopper and InComponentClass('Mounting Holes')] p3: gap=39.37 ignorepadtopadclearanceinfootprint=FALSE
BoardOutlineClearance BoardOutlineClearance_Poly [OnCopper and IsPoly] p4: gap=25 ignorepadtopadclearanceinfootprint=FALSE // for non-ground polygons pull back
BoardOutlineClearance [OnCopper and Not InComponentClass('Logo') and not InComponentClass('FiducialMark') and not InRegion(1000,500,4000,800) and not InPoly and not HasFootprint('cbts130a')] p5: gap=25 ignorepadtopadclearanceinfootprint=FALSE
Clearance Clearance_Poly_GND [InPolygon and InNet('GND')] p1: gap=5 ignorepadtopadclearanceinfootprint=TRUE except(8: Arc-Hole Track-Hole SMDPad-Hole THPad-Hole Via-Hole Fill-Hole Poly-Hole Region-Hole Text-Hole; 15: Fill-Fill Fill-Poly Fill-Region Poly-Poly Poly-Region Region-Region)
Clearance Clearance_Keepouts [((IsTrack Or IsArc) And Not InPoly) And IsFree and IsKeepOut vs ((IsTrack Or IsArc) And Not InPoly) And IsFree and IsKeepOut] p2: gap=0 ignorepadtopadclearanceinfootprint=FALSE
Clearance Clearance_Poly [InPolygon] p3: gap=5 ignorepadtopadclearanceinfootprint=TRUE except(8: Arc-Hole Track-Hole SMDPad-Hole THPad-Hole Via-Hole Fill-Hole Poly-Hole Region-Hole Text-Hole; 15: Fill-Fill Fill-Poly Fill-Region Poly-Poly Poly-Region Region-Region)
Clearance Clearance_FiducialMark [IsKeepOut and InComponentClass('FiducialMark') vs IsPad and InComponentClass('FiducialMark')] p4: gap=0 ignorepadtopadclearanceinfootprint=FALSE
Clearance Clearance_Outter_Layers [All vs OnLayer('Top Layer') or OnLayer('Bottom Layer') and not InAnyDifferentialPair] p5: gap=5 ignorepadtopadclearanceinfootprint=TRUE except(4: Arc-Arc Arc-Track Track-Track; 8: Arc-Hole Track-Hole SMDPad-Hole THPad-Hole Via-Hole Fill-Fill Fill-Poly Fill-Region Fill-Hole Poly-Poly Poly-Region Poly-Hole Region-Region Region-Hole Text-Hole; 10: SMDPad-SMDPad THPad-Fill THPad-Poly THPad-Region)
Clearance Clearance_Inner_Layers [All vs not OnLayer('Top Layer') and not OnLayer('Bottom Layer') and not InAnyDifferentialPair] p6: gap=5 ignorepadtopadclearanceinfootprint=TRUE except(8: Arc-Hole Track-Hole SMDPad-Hole THPad-Hole Via-Hole Fill-Hole Poly-Hole Region-Hole Text-Hole; 10: SMDPad-SMDPad THPad-Fill THPad-Poly THPad-Region; 15: Arc-Fill Arc-Poly Arc-Region Track-Fill Track-Poly Track-Region Fill-Fill Fill-Poly Fill-Region Poly-Poly Poly-Region Region-Region)
ComponentClearance "ComponentClearance Part Overlap" [All] p1: gap=0 collisioncheckmode=3 verticalgap=0 showdistances=FALSE
ComponentClearance ComponentClearance_MountingHoles_FiducialMarks [InComponentClass('Mounting Holes') vs InComponentClass('FiducialMark')] p2: gap=50 collisioncheckmode=3 verticalgap=10 showdistances=FALSE
ComponentClearance ComponentClearance_Shunt [InComponentClass('Header') vs InComponentClass('Shunt')] p3: gap=0 collisioncheckmode=3 verticalgap=0 showdistances=FALSE
ComponentClearance ComponentClearance_Logo [InComponentClass('Logo')] p4: gap=50 collisioncheckmode=3 verticalgap=10 showdistances=FALSE
ComponentClearance ComponentClearance_ScrewToNut [(HasFootprint('NY PMS 440 0025 PH')) vs (HasFootprint('Keystone_1902C'))] p5: gap=5 collisioncheckmode=3 verticalgap=10 showdistances=FALSE
ComponentClearance ComponentClearance_MountingHoles [InComponentClass('Mounting Holes')] p6: gap=100 collisioncheckmode=3 verticalgap=100000 showdistances=FALSE
ComponentClearance ComponentClearance_SmallPassives [HasFootprint('0201*') or HasFootprint('0402*') or HasFootprint('0508') or HasFootprint('0603*') or HasFootprint('0612') or HasFootprint('0805*') or HasFootprint('0815*') or HasFootprint('0830*') or HasFootprint('1206*') or HasFootprint('1210*') or HasFootprint('1808*') or HasFootprint('1812*') or HasFootprint('1825*') or HasFootprint('2010*') or HasFootprint('2220*') or HasFootprint('2225*') or HasFootprint('2512*') or HasFootprint('2728*') or HasFootprint('3518*') vs HasFootprint('0201*') or HasFootprint('0402*') or HasFootprint('0508') or HasFootprint('0603*') or HasFootprint('0612') or HasFootprint('0805*') or HasFootprint('0815*') or HasFootprint('0830*') or HasFootprint('1206*') or HasFootprint('1210*') or HasFootprint('1808*') or HasFootprint('1812*') or HasFootprint('1825*') or HasFootprint('2010*') or HasFootprint('2220*') or HasFootprint('2225*') or HasFootprint('2512*') or HasFootprint('2728*') or HasFootprint('3518*')] p7: gap=10 collisioncheckmode=3 verticalgap=10 showdistances=FALSE
ComponentClearance ComponentClearance_THtoSMT [IsThruComponent and not HasFootprint('ProbePoint_TH_40mil') vs IsSMTComponent] p8: gap=20 collisioncheckmode=3 verticalgap=0 showdistances=FALSE
ComponentClearance ComponentClearance_THtoTH [IsThruComponent and not HasFootprint('ProbePoint_TH_40mil') vs IsThruComponent and not HasFootprint('ProbePoint_TH_40mil')] p9: gap=30 collisioncheckmode=3 verticalgap=30 showdistances=FALSE
ComponentClearance [All] p10: gap=10 collisioncheckmode=3 verticalgap=10 showdistances=FALSE
DiffPairsRouting [All] p1: maxlimit=10 minlimit=3 mostfreqgap=10 toplayer_prefgap=4 toplayer_minwidth=5 toplayer_maxwidth=15 toplayer_prefwidth=5.2 midlayer1_minwidth=5 midlayer1_maxwidth=15 midlayer1_prefwidth=15 midlayer2_minwidth=5 midlayer2_maxwidth=15 midlayer2_prefwidth=15 midlayer3_minwidth=5 midlayer3_maxwidth=15 midlayer3_prefwidth=15 midlayer4_minwidth=5 midlayer4_maxwidth=15 midlayer4_prefwidth=15 midlayer5_minwidth=5 midlayer5_maxwidth=15 midlayer5_prefwidth=15 midlayer6_minwidth=5 midlayer6_maxwidth=15 midlayer6_prefwidth=15 midlayer7_minwidth=5 midlayer7_maxwidth=15 midlayer7_prefwidth=15 midlayer8_minwidth=5 midlayer8_maxwidth=15 midlayer8_prefwidth=15 bottomlayer_prefgap=4 bottomlayer_minwidth=5 bottomlayer_maxwidth=15 bottomlayer_prefwidth=5.2 maxuncoupledlength=500
FabricationTestPointUsage TestPointUsage [All] p1: valid=2 allowmultiple=FALSE
FabricationTestpoint Testpoint [All] p1: side=3 testpointundercomponent=TRUE minsize=40 maxsize=100 preferedsize=60 minholesize=0 maxholesize=40 preferedholesize=32 testpointgrid=1 allowsidetop=TRUE allowsidebottom=TRUE usegrid=TRUE gridtolerance=0.01
FanoutControl Fanout_LCC [IsLCC] p1: bgadir=Out bgaviamode=Centered fanoutstyle=Auto fanoutdirection=Alternating viagrid=1 // Fanout_LCC (Default Rule)
FanoutControl Fanout_BGA [IsBGA] p2: bgadir=Out bgaviamode=Centered fanoutstyle=Auto fanoutdirection=Alternating viagrid=1 // Fanout_BGA (Default Rule)
FanoutControl Fanout_Default [All] p4: bgadir=Out bgaviamode=Centered fanoutstyle=Auto fanoutdirection=Alternating viagrid=1 // Fanout_Default (Default Rule)
FanoutControl Fanout_Small [(CompPinCount < 5)] p5: bgadir=Out bgaviamode=Centered fanoutstyle=Auto fanoutdirection=OutThenIn viagrid=1 // Fanout_Small (Default Rule)
HoleSize [All] p1: absolutevalues=TRUE maxlimit=2500 minlimit=5 maxpercent=80.000 minpercent=20.000
HoleToHoleClearance [All] p1: gap=8 allowstackedmicrovias=TRUE
MatchedLengths Intrapair [InNetClass('DiffPair')] p1: tolerance=10 checknetsindiffpair=FALSE checkdiffpairvsdiffpair=TRUE checkxsignals=TRUE checkothers=TRUE
MatchedLengths Interpair [InNetClass('DiffPair')] p2: tolerance=4 checknetsindiffpair=TRUE checkdiffpairvsdiffpair=FALSE checkxsignals=FALSE checkothers=FALSE
MinimumSolderMaskSliver MinimumSolderMaskSliver_Logo [InComponentClass('Logo') vs InComponentClass('Logo')] p1: minsoldermaskwidth=0.7
MinimumSolderMaskSliver [All] p2: minsoldermaskwidth=3
PlaneConnect [All] p1: planeconnectstyle=Relief reliefexpansion=10 reliefentries=4 reliefconductorwidth=10 reliefairgap=10
PolygonConnect Thermals_USB [IsPolygon vs HasFootprint('Hirose_UX60SC-MB-5S8')] p1: thpad.connectstyle=Relief thpad.reliefconductorwidth=15 thpad.reliefentries=4 thpad.polygonreliefangle="90 Angle" thpad.airgapwidth=10 smdpad.connectstyle=Direct smdpad.reliefconductorwidth=10 smdpad.reliefentries=4 smdpad.polygonreliefangle="90 Angle" smdpad.airgapwidth=10 via.connectstyle=Direct via.reliefconductorwidth=10 via.reliefentries=4 via.polygonreliefangle="90 Angle" via.airgapwidth=10
PolygonConnect Thermals [IsPolygon vs (IsPad and HoleSize <= 41) or HasFootprint('500ASSP1M2QE')] p2: connectstyle=Direct reliefconductorwidth=10 reliefentries=4 polygonreliefangle="90 Angle" airgapwidth=10
PolygonConnect [All] p3: thpad.connectstyle=Relief thpad.reliefconductorwidth=20 thpad.reliefentries=4 thpad.polygonreliefangle="45 Angle" thpad.airgapwidth=10 smdpad.connectstyle=Direct smdpad.reliefconductorwidth=10 smdpad.reliefentries=4 smdpad.polygonreliefangle="90 Angle" smdpad.airgapwidth=10 via.connectstyle=Direct via.reliefconductorwidth=10 via.reliefentries=4 via.polygonreliefangle="90 Angle" via.airgapwidth=10
RoutingVias [All] p1: holewidth=28 width=50 viastyle="Through Hole" minholewidth=28 minwidth=50 maxholewidth=28 maxwidth=50
SMDEntry [All] p1: side=TRUE corner=TRUE anyangle=FALSE
SMDToCorner [All] p1: distance=0
SilkToBoardRegionClearance [Not ((IsComment or IsDesignator) And (Hide <> 'False')) and not InRegion(1000,500,4000,800)] p1:
SilkToSilkClearance [All] p1: silktosilkclearance=0.1
SilkToSolderMaskClearance SilkToComponentPadClearance [(IsPad or IsFill or IsRegion) and InAnycomponent] p1: minsilkscreentomaskgap=3 clearancetoexposedcopper=TRUE
SilkToSolderMaskClearance "Silk to Solder Mask Opening" [All] p2: minsilkscreentomaskgap=0 clearancetoexposedcopper=FALSE
SolderMaskExpansion [All] p1: expansion=1.97 istentingtop=FALSE
SupplyNets "Schematic Supply Nets_13" [InNet('1p8V_LVLSHIFT')] p1: voltage=0.000
SupplyNets "Schematic Supply Nets_12" [InNet('VCM')] p2: voltage=0.000
SupplyNets "Schematic Supply Nets_11" [InNet('3p3V_EEPROM')] p3: voltage=0.000
SupplyNets "Schematic Supply Nets_10" [InNet('3p3V_AUX')] p4: voltage=0.000
SupplyNets "Schematic Supply Nets_9" [InNet('12V_FMC')] p5: voltage=0.000
SupplyNets "Schematic Supply Nets_8" [InNet('GND')] p6: voltage=0.000
SupplyNets "Schematic Supply Nets_7" [InNet('VADJ')] p7: voltage=0.000
SupplyNets "Schematic Supply Nets_6" [InNet('1p8V_AVDD')] p8: voltage=0.000
SupplyNets "Schematic Supply Nets_5" [InNet('1p8V_IOVDD')] p9: voltage=0.000
SupplyNets "Schematic Supply Nets_4" [InNet('2p3V')] p10: voltage=0.000
SupplyNets "Schematic Supply Nets_3" [InNet('USB_5V')] p11: voltage=0.000
SupplyNets "Schematic Supply Nets_2" [InNet('12V')] p12: voltage=0.000
SupplyNets "Schematic Supply Nets_1" [InNet('VREF')] p13: voltage=0.000
SupplyNets "Schematic Supply Nets" [InNet('3p3V_Utility')] p14: voltage=0.000
UnRoutedNet [All] p1: checkbadconnections=TRUE
Width [All] p1: maxlimit=100 minlimit=5 preferedwidth=5 toplayer_prefwidth=9.7 bottomlayer_prefwidth=9.7 minimp=50.000000 maximp=50.000000 favimp=50.000000
13 further rules are at their usual default settings.

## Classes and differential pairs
component class Shunt: SH-J1 SH-J2
net class DiffPairIN: AIN_N AIN_P BIN_N BIN_P CLK_N CLK_P
net class DUTPwr: 1p8V_AVDD 1p8V_IOVDD
net class Power: 1p8V_AVDD 1p8V_IOVDD 2p3V 3p3V_Utility 12V VADJ
net class GenPwr: 2p3V 3p3V_Utility 12V
net class FMCPwr: VADJ
net class DiffPair: DA0_DUT_N DA0_DUT_P DA0_N DA0_P DA1_DUT_N DA1_DUT_P DA1_N DA1_P DB0_DUT_N DB0_DUT_P DB0_N DB0_P DB1_DUT_N DB1_DUT_P DB1_N DB1_P DCLK_DUT_N DCLK_DUT_P DCLK_N DCLK_P DCLKIN_DUT_N DCLKIN_DUT_P FCLK_DUT_N FCLK_DUT_P FCLK_N FCLK_P
component class "CLK and DCLKIN": C48 C49 C50 C51 C52 C53 C54 C55 C56 C57 J4 J5 J6 R62 R63 R64 R65 R66 R67 R68 R69 R70 R71 R72 R73 R74 R75 SW3 T1 U17 U18
component class "ADC Inputs": C58 C59 C60 C61 C62 C63 C64 C65 C66 C67 C68 C69 C70 C71 C72 C73 J7 J8 J9 J10 L1 L2 L3 L4 R76 R77 R78 R79 R80 R81 R82 R83 R84 R85 R86 R87 R88 R89 R90 R91 R92 R93 R94 R95 R96 R97 R98 R99 T2 T3
component class "Power DC-DC": C9 C10 C11 C12 C13 C14 C15 C16 FB1 PP2 R9 R10 R11 R12 R13 R14 U4
component class "Power LDO": C17 C18 C19 C20 C21 C22 C23 C24 C25 C26 C27 C28 D4 D5 FB2 FB3 PP3 PP4 Q2 Q3 R15 R16 R17 R18 R19 R20 R21 R22 R23 R24 R25 R26 R27 R28 R29 R30 R31 U5 U6 U7 U8
component class "Power Sense ADC": C29 R32 R33 U9
component class "DUT IO": C74 C75 C76 C77 C78 C79 C80 C81 C82 C83 C84 C85 C86 C87 C88 J11 J12 J13 PP10 R100 R101 R102 R103 R104 R105 R106 R107 R108 R109 R110 R111 R112 R113 R114 R115 R116 R117 R118 R119 R120 R121 R122 R123 R124 R125 R126 R127 R128 R129 R130 R131 R132 R133 SH-J1 SH-J2 SW4 SW5 TP3 U1 U19 U20 U21
component class "Comms LVL Shift and MUX": C44 C45 C46 C47 PP5 PP6 PP7 PP8 PP9 R51 R52 R53 R54 R55 R56 R57 R58 R59 R60 R61 R147 R148 R149 R150 SW2 U13 U14 U15 U16 U23
component class "FMC+ Sections F-H, J, K": R142 R143 R144 R145 R146 R151
component class "USB Control FTDI": C30 C31 C32 C33 C34 C35 C36 C37 C38 C39 C40 C41 C42 C43 D6 FB4 FB5 J3 R34 R35 R36 R37 R38 R39 R40 R41 R42 R43 R44 R45 R46 R47 R48 R49 R50 U10 U11 U12 Y1
component class "12V Input, Efuse and 3p3V Utility": C1 C2 C3 C4 C5 C6 C7 C8 D1 D2 D3 F1 J2 PP1 Q1 R1 R2 R3 R4 R5 R6 R7 R8 SW1 TP1 TP2 U2 U3
component class "FMC+ Sections A-E": C89 J1 R134 R135 R136 R137 R138 R139 R140 R141 U22
component class "Hardware & Mechanicals": !PCB? FID1 FID2 FID3 H1 H3 LBL1 Logo1 Logo2 Logo3 Logo4 LOGO5 Logo6 ZZ1
differential pair FCLK_DUT: +FCLK_DUT_P -FCLK_DUT_N
differential pair DCLKIN_DUT: +DCLKIN_DUT_P -DCLKIN_DUT_N
differential pair DCLK_DUT: +DCLK_DUT_P -DCLK_DUT_N
differential pair DB1_DUT: +DB1_DUT_P -DB1_DUT_N
differential pair DB0_DUT: +DB0_DUT_P -DB0_DUT_N
differential pair DA1_DUT: +DA1_DUT_P -DA1_DUT_N
differential pair DA0_DUT: +DA0_DUT_P -DA0_DUT_N
differential pair SMA_CLK: +SMA_CLK_P -SMA_CLK_N
differential pair FPGA_DCLKIN: +FPGA_DCLKIN_P -FPGA_DCLKIN_N
differential pair FCLK: +FCLK_P -FCLK_N
differential pair DCLK: +DCLK_P -DCLK_N
differential pair DCLKIN: +DCLKIN_P -DCLKIN_N
differential pair DCLKIN_SMA: +DCLKIN_SMA_P -DCLKIN_SMA_N
differential pair DB1: +DB1_P -DB1_N
differential pair DB0: +DB0_P -DB0_N
differential pair DA1: +DA1_P -DA1_N
differential pair DA0: +DA0_P -DA0_N
differential pair CLK: +CLK_P -CLK_N
differential pair BIN: +BIN_P -BIN_N
differential pair AIN: +AIN_P -AIN_N

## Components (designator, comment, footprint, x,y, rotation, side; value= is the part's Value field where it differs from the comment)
C1 "C2012X7R1H105K125AB" 0805L_cap 832.9,516.43 r90 bottom value="1 uF"
C2 "C2012X7R1H105K125AB" 0805L_cap 1233.56,533.64 r180 bottom value="1 uF"
C3 "C2012X7R1H105K125AB" 0805L_cap 1233.56,463.64 r180 bottom value="1 uF"
C4 "CGA3E2X7R1H102K080AA" 0603L_cap 1304.09,248.4 r180 bottom value="0.001 uF"
C5 "CGA3E2X7R1H102K080AA" 0603L_cap 1322.87,298.4 r180 bottom value="0.001 uF"
C6 "C2012X7S1E106K125AC" 0805L_cap 1198.13,628.89 r270 bottom value="10 uF"
C7 "C2012X7S1A226M125AC" 0805L_cap 952.5,621.47 r90 bottom value="22 uF"
C8 "CGA2B2X7R1H332K050BA" 0402L_cap#1 1133.88,704.14 r90 bottom value="3300 pF"
C9 "C2012X7S1E106K125AC" 0805L_cap 392.26,964.72 r270 bottom value="10 uF"
C10 "C2012X7S1E106K125AC" 0805L_cap 322.26,964.72 r270 bottom value="10 uF"
C11 "C2012X7S1A226M125AC" 0805L_cap 156.79,1155 r0 bottom value="22 uF"
C12 "C2012X7S1A226M125AC" 0805L_cap 156.79,1225.06 r0 bottom value="22 uF"
C13 "C2012X7S1A226M125AC" 0805L_cap 280.8,1155 r180 bottom value="22 uF"
C14 "C2012X7S1A226M125AC" 0805L_cap 220.8,1338.49 r0 bottom value="22 uF"
C15 "C2012X7S1A226M125AC" 0805L_cap 344.81,1338.49 r180 bottom value="22 uF"
C16 "CGA2B1X5R1C224M050BC" 0402L_cap#1 217.89,816.44 r270 bottom value="0.22 uF"
C17 "GRT155R71E104KE01J" 0402L_cap#1 941.14,1550.75 r0 top value="0.1 uF"
C18 "C2012X7S1E106K125AC" 0805L_cap 480.98,1598.19 r270 top value="10 uF"
C19 "GRT155R71E104KE01J" 0402L_cap#1 536.41,1578.51 r270 top value="0.1 uF"
C20 "C2012X7S1E106K125AC" 0805L_cap 793.72,1575.5 r270 top value="10 uF"
C21 "GRM188R60J476ME15D" 0603L_cap 768.74,1755.8 r270 top value="47 uF"
C22 "C1005X5R1E105K050BC" 0402L_cap#2 712.72,1485.59 r90 top value="1 uF"
C23 "GRT155R71E104KE01J" 0402L_cap#1 941.14,1150.75 r0 top value="0.1 uF"
C24 "C2012X7S1E106K125AC" 0805L_cap 480.98,1198.19 r270 top value="10 uF"
C25 "GRT155R71E104KE01J" 0402L_cap#1 536.41,1178.5 r270 top value="0.1 uF"
C26 "C2012X7S1E106K125AC" 0805L_cap 793.72,1175.5 r270 top value="10 uF"
C27 "GRM188R60J476ME15D" 0603L_cap 768.74,1355.8 r270 top value="47 uF"
C28 "C1005X5R1E105K050BC" 0402L_cap#2 712.72,1085.59 r90 top value="1 uF"
C29 "GRT155R71E104KE01J" 0402L_cap#1 1229.95,1859.23 r0 bottom value="0.1 uF"
C30 "GRT155R71E104KE01J" 0402L_cap#1 670.29,2168.6 r270 bottom value="0.1 uF"
C31 "C1005X5R1A475K050BC" 0402L_cap#1 377.37,2160.56 r90 top value="4.7 uF"
C32 "GRT155R71E104KE01J" 0402L_cap#1 411.37,2160.56 r90 top value="0.1 uF"
C33 "C1005X5R1A475K050BC" 0402L_cap#1 376,2326.08 r270 top value="4.7 uF"
C34 "GRT155R71E104KE01J" 0402L_cap#1 410,2326.08 r270 top value="0.1 uF"
C35 "CGA3E1X5R1A335K080AC" 0603L_cap 846.42,2148.91 r0 bottom value="3.3 uF"
C36 "GRT155R71E104KE01J" 0402L_cap#1 847.98,2267.02 r270 bottom value="0.1 uF"
C37 "GRT155R71E104KE01J" 0402L_cap#1 509.93,2109.54 r0 bottom value="0.1 uF"
C38 "GRT155R71E104KE01J" 0402L_cap#1 620.59,2048.32 r180 bottom value="0.1 uF"
C39 "GRT155R71E104KE01J" 0402L_cap#1 699.33,2511.98 r270 bottom value="0.1 uF"
C40 "GRT155R71E104KE01J" 0402L_cap#1 837.13,2033.32 r180 bottom value="0.1 uF"
C41 "GRT155R71E104KE01J" 0402L_cap#1 817.44,2362.61 r90 bottom value="0.1 uF"
C42 "GJM0336C1E180JB01J" 0201_cap 313.91,2417.36 r135 top value="18 pF"
C43 "GJM0336C1E180JB01J" 0201_cap 508.05,2611.5 r135 top value="18 pF"
C44 "GRT155R71E104KE01J" 0402L_cap#1 1242.17,2323.6 r0 top value="0.1 uF"
C45 "GRT155R71E104KE01J" 0402L_cap#1 1008.98,2088.62 r90 top value="0.1 uF"
C46 "GRT155R71E104KE01J" 0402L_cap#1 1099.53,2088.62 r90 top value="0.1 uF"
C47 "GRT155R71E104KE01J" 0402L_cap#1 1229.33,2165.39 r0 top value="0.1 uF"
C48 "GRM033Z71C104ME14D" 0201_cap 1967.18,1244.35 r0 top value="0.1 uF"
C49 "GRM033Z71C104ME14D" 0201_cap 1872.13,1266.57 r0 top value="0.1 uF"
C50 "GRM033Z71C104ME14D" 0201_cap 1495.08,1233.05 r180 top value="0.1 uF"
C51 "GRM033Z71C104ME14D" 0201_cap 1877.08,1233.05 r0 top value="0.1 uF"
C52 "GRM033Z71C104ME14D" 0201_cap 1461.11,969.07 r270 top value="0.1 uF"
C53 "GRM033Z71C104ME14D" 0201_cap 1872.13,1199.53 r180 top value="0.1 uF"
C54 "GRM033Z71C104ME14D" 0201_cap 1967.18,1221.75 r0 top value="0.1 uF"
C55 "GRT155R71E104KE01J" 0402L_cap#1 2832.1,1088.72 r0 top value="0.1 uF"
C56 "GRM033Z71C104ME14D" 0201_cap 2862.58,1027.4 r90 bottom value="0.1 uF"
C57 "GRM033Z71C104ME14D" 0201_cap 2882.27,826.72 r270 top value="0.1 uF"
C58 "GRM033Z71C104ME14D" 0201_cap 1863.45,409.74 r90 top value="0.1 uF"
C59 "GRM033Z71C104ME14D" 0201_cap 1874.47,398.72 r0 top value="0.1 uF"
C60 "GRM033Z71C104ME14D" 0201_cap 2104.93,809.74 r90 top value="0.1 uF"
C61 "GRM033Z71C104ME14D" 0201_cap 2138.45,983.24 r90 top value="0.1 uF"
C62 "GRM033Z71C104ME14D" 0201_cap 2138.45,804.74 r90 top value="0.1 uF"
C63 "CGA1A2X7R1E101M030BA" 0201_cap 2138.95,885.81 r180 top value="100 pF"
C64 "GRM033Z71C104ME14D" 0201_cap 2172.95,809.74 r270 top value="0.1 uF"
C65 "GRM033Z71C104ME14D" 0201_cap 2413.45,409.74 r90 top value="0.1 uF"
C66 "GRM033Z71C104ME14D" 0201_cap 2412.46,2087.85 r270 top value="0.1 uF"
C67 "GRM033Z71C104ME14D" 0201_cap 2401.44,2098.88 r180 top value="0.1 uF"
C68 "GRM033Z71C104ME14D" 0201_cap 2171.97,1687.85 r270 top value="0.1 uF"
C69 "GRM033Z71C104ME14D" 0201_cap 2138.45,1512.97 r270 top value="0.1 uF"
C70 "GRM033Z71C104ME14D" 0201_cap 2137.46,1692.85 r270 top value="0.1 uF"
C71 "CGA1A2X7R1E101M030BA" 0201_cap 2137.94,1611.78 r0 top value="100 pF"
C72 "GRM033Z71C104ME14D" 0201_cap 2104.93,1687.85 r90 top value="0.1 uF"
C73 "GRM033Z71C104ME14D" 0201_cap 1862.46,2087.85 r270 top value="0.1 uF"
C74 "GRM033R61A105ME44D" 0201_cap 2177.82,1155.91 r270 bottom value="1 uF"
C75 "GRM033Z71C104ME14D" 0201_cap 2093.51,1256.67 r180 bottom value="0.1 uF"
C76 "GRM033Z71C104ME14D" 0201_cap 2170,1380 r270 bottom value="0.1 uF"
C77 "GRM033R61A105ME44D" 0201_cap 2287.97,1165.14 r135 bottom value="1 uF"
C78 "GRM033Z71C104ME14D" 0201_cap 2287.97,1332.46 r225 bottom value="0.1 uF"
C79 "GRM033R61A105ME44D" 0201_cap 2049.75,1210.43 r0 bottom value="1 uF"
C80 "GRM033Z71C104ME14D" 0201_cap 2093.51,1210.43 r180 bottom value="0.1 uF"
C81 "GRT155R71E104KE01J" 0402L_cap#1 1563.61,691.02 r90 bottom value="0.1 uF"
C82 "GRT155R71E104KE01J" 0402L_cap#1 1506.58,483.65 r0 bottom value="0.1 uF"
C83 "0402ZD106MAT2A" 0402L_cap#1 2090.89,1298.92 r180 bottom value="10 uF"
C84 "GRM033Z71C104ME14D" 0201_cap 2082.23,1326.92 r180 bottom value="0.1 uF"
C85 "GRM033Z71C104ME14D" 0201_cap 2051.18,1298.92 r0 top value="0.1 uF"
C86 "GRT155R71E104KE01J" 0402L_cap#1 2032.8,1500.86 r135 bottom value="0.1 uF"
C87 "0402ZD106MAT2A" 0402L_cap#1 2021.52,1272.42 r0 bottom value="10 uF"
C88 "GRM033Z71C104ME14D" 0201_cap 2025.18,1248.42 r0 bottom value="0.1 uF"
C89 "GRT155R71E104KE01J" 0402L_cap#1 3221.49,194.99 r180 top value="0.1 uF"
D1 "LTST-C191TGKT" LED_LTST-C190-Green 325.14,119.85 r0 top
D2 "SMBJ15CA" SMBJ15CA 961.01,303.18 r90 bottom
D3 "MBR130T1G" SOD-123 1061.77,539.36 r180 bottom
D4 "LTST-C191TGKT" LED_LTST-C190-Green 1065,2633.58 r270 top
D5 "LTST-C191TGKT" LED_LTST-C190-Green 1160,2633.58 r270 top
D6 "LTST-C191TGKT" LED_LTST-C190-Green 310,2050 r0 top
F1 "BNX002-11" FIL_BNX002-11 734.47,319.58 r90 top
FB1 "BLE18PS080SN1D" 0603L 255.58,1257.62 r90 bottom value=-
FB2 "BLM21SP471SN1D" 0805L 844.27,1716.43 r180 top value=-
FB3 "BLM21SP471SN1D" 0805L 844.27,1316.43 r180 top value=-
FB4 "NFZ15SG151SN11D" 0402L#1 341.37,2160.56 r90 top value=-
FB5 "NFZ15SG151SN11D" 0402L#1 340,2326.08 r270 top value=-
FID1 "Fiducial Mark" Fiducial10-20 281.88,50 r90 top
FID2 "Fiducial Mark" Fiducial10-20 3720,110 r90 top
FID3 "Fiducial Mark" Fiducial10-20 3361.42,2598.27 r90 top
H1 "CBTS130A" cbts130a 130,2595 r0 top locked
H3 "CBTS130A" cbts130a 125,125 r0 top
J1 "ASP-134488-01" SAMTEC_ASP-134488-01 3586.42,1359.27 r90 bottom locked
J2 "RAPC722X" RAPC722X -148.41,443 r0 top
J3 "USB4105-GF-A" FP-USB4105-GF-A_CONN_USB_9MM58_7MM53-MFG 108.82,2257.18 r270 top
J4 "132134-15" FP-132134-15_CONN_SMA_JACK-MFG 1261.11,1508.05 r0 top
J5 "132134-15" FP-132134-15_CONN_SMA_JACK-MFG 1261.11,958.05 r0 top
J6 "132134-15" FP-132134-15_CONN_SMA_JACK-MFG 2882.27,625.27 r0 top
J7 "132134-15" FP-132134-15_CONN_SMA_JACK-MFG 1863.45,198.72 r0 top
J8 "132134-15" FP-132134-15_CONN_SMA_JACK-MFG 2413.45,198.72 r0 top
J9 "132134-15" FP-132134-15_CONN_SMA_JACK-MFG 2412.46,2298.88 r0 top
J10 "132134-15" FP-132134-15_CONN_SMA_JACK-MFG 1862.46,2298.88 r0 top
J11 "132134-15" FP-132134-15_CONN_SMA_JACK-MFG 2972.46,2238.88 r0 top
J12 "TSW-103-14-L-S" PBC03SAAN 2672.25,1888.88 r270 top
J13 "GRPB021VWVN-RC" HDR_2x1_TH_VT_50mil 2005.08,1425.37 r315 top
L1 "LQG15HSR18J02D" IND_LQG15H 2104.93,927.51 r90 top value=180nH
L2 "LQG15HSR18J02D" IND_LQG15H 2171.97,927.51 r90 top value=180nH
L3 "LQG15HSR18J02D" IND_LQG15H 2171.97,1570.08 r270 top value=180nH
L4 "LQG15HSR18J02D" IND_LQG15H 2104.93,1570.08 r270 top value=180nH
LBL1 "THT-14-423-10" Label_650x200 3740,1420 r270 top
Logo1 "FDL Logo" FDL_Small 3695,230 r0 top
Logo2 "FCC disclaimer" FCC_disclaimer 2695,2293.66 r90 bottom
Logo3 "ESD Overlay" ESD_Overlay_Small 2510,1357.74 r0 top
Logo4 "WEEE" WEEE_Minimum 1670,1990 r180 bottom
LOGO5 "CE Mark" CE_Mark_5mm 3123.58,2560 r180 bottom
Logo6 "Texas Instruments" TI_Stacked_Overlay_Small_Vertical 3473.23,1903.13 r270 top
PP1 "Probe Point" ProbePoint_TH_40mil 952.5,720.99 r180 top
PP2 "Probe Point" ProbePoint_TH_40mil 318.14,1245.07 r90 bottom
PP3 "Probe Point" ProbePoint_TH_40mil 824.74,1786.43 r180 top
PP4 "Probe Point" ProbePoint_TH_40mil 824.74,1386.43 r180 top
PP5 "Probe Point" ProbePoint_TH_40mil 1351.85,2284.23 r0 top
PP6 "Probe Point" ProbePoint_TH_40mil 1351.85,2362.97 r0 top
PP7 "Probe Point" ProbePoint_TH_40mil 1385,2125.97 r0 top
PP8 "Probe Point" ProbePoint_TH_40mil 1385,2245.97 r0 top
PP9 "Probe Point" ProbePoint_TH_40mil 1385,2185.97 r0 top
PP10 "Probe Point" ProbePoint_TH_40mil 1458.21,710.71 r180 top
Q1 "CSD15571Q2" DQK0006C 837.23,318.16 r270 bottom
Q2 "CSD13380F3" YJM0003A 1101.89,2653.11 r0 bottom
Q3 "CSD13380F3" YJM0003A 1196.89,2653.11 r0 bottom
R1 "ERA-2AED104X" 0402L#2 1216.76,258.4 r180 bottom value="100 kΩ"
R2 "ERJ-2RKF4532X" 0402L#2 1310.27,408.64 r180 bottom value="45.3 kΩ"
R3 "ERJ-HP6F1002V" 0805L 684.2,119.85 r180 bottom value="10 kΩ"
R4 "ERA-2AEB1622X" 0402L#2 1296.62,205.62 r180 bottom value="16.2 kΩ"
R5 "ERA-2AEB103X" 0402L#2 1069.29,779.51 r90 bottom value="10 kΩ"
R6 "ERA-2AEB103X" 0402L#2 1133.88,621.47 r270 bottom value="10 kΩ"
R7 "ERA-2AEB3742X" 0402L#2 1035.7,779.51 r90 bottom value="37.4 kΩ"
R8 "ERJ-2RKF1202X" 0402L#2 1002.1,779.51 r270 bottom value="12 kΩ"
R9 "ERJ-U020R00X" 0402L#2 1121.72,759.83 r180 bottom value="0 Ω"
R10 "ERA-2AEB103X" 0402L#2 251.89,816.44 r270 bottom value="10 kΩ"
R11 "ERJ-2RKF1002X" 0402L#2 81.89,816.44 r270 bottom value="10 kΩ"
R12 "ERA-2AEB9311X" 0402L#2 183.89,816.44 r270 bottom value="9.31 kΩ"
R13 "ERJ-2RKF8062X" 0402L#2 115.89,816.44 r90 bottom value="80.6 kΩ"
R14 "ERA-2AEB4871X" 0402L#2 149.89,816.44 r90 bottom value="4.87 kΩ"
R15 "ERA-2AEB103X" 0402L#2 522.48,1485.59 r270 top value="10 kΩ"
R16 "ERJ-2RKF1002X" 0402L#2 519.61,1532.05 r180 bottom value="10 kΩ"
R17 "WSLP0603R1000FEA" CCS0603FLxLxx 858.46,1590.51 r90 top value="100 mΩ"
R18 "ERJ-HP6F1002V" 0805L 1065,2544.53 r90 bottom value="10 kΩ"
R19 "RT0402BRD0788K7L" 0402L#2 709.12,1571.42 r270 top value="88.7 kΩ"
R20 "ERA-2AEB1242X" 0402L#2 742.72,1610.79 r270 top value="12.4 kΩ"
R21 "ERJ-2RKF1202X" 0402L#1 747.72,1485.59 r90 top value="12 kΩ"
R22 "ERJ-U020R00X" 0402L#2 801.4,1465.91 r180 top value="0 Ω"
R23 "ERJ-U020R00X" 0402L#2 341.79,836.12 r180 bottom value="0 Ω"
R24 "ERA-2AEB103X" 0402L#2 522.48,1085.59 r270 top value="10 kΩ"
R25 "ERJ-HP6F1002V" 0805L 1160,2544.53 r90 bottom value="10 kΩ"
R26 "ERJ-2RKF1002X" 0402L#2 519.61,1132.05 r180 bottom value="10 kΩ"
R27 "WSLP0603R1000FEA" CCS0603FLxLxx 858.46,1190.51 r90 top value="100 mΩ"
R28 "RT0402BRD0788K7L" 0402L#2 709.12,1171.42 r270 top value="88.7 kΩ"
R29 "ERA-2AEB1242X" 0402L#2 742.72,1210.79 r270 top value="12.4 kΩ"
R30 "ERJ-2RKF1202X" 0402L#1 747.72,1085.59 r90 top value="12 kΩ"
R31 "ERJ-U020R00X" 0402L#2 801.4,1065.91 r180 top value="0 Ω"
R32 "ERA-2AEB103X" 0402L#2 1204.09,2027.82 r180 bottom value="10 kΩ"
R33 "ERA-2AEB103X" 0402L#2 1353.7,2027.82 r0 bottom value="10 kΩ"
R34 "ERA-2AEB103X" 0402L#2 699.33,2106.22 r180 bottom value="10 kΩ"
R35 "ERA-2AEB103X" 0402L#2 738.7,2321.95 r270 bottom value="10 kΩ"
R36 "ERJ-1GN0R00C" 0201 403.98,2070.17 r180 top value="0 Ω"
R37 "ERA-2AEB103X" 0402L#2 699.33,2321.95 r90 bottom value="10 kΩ"
R38 "ERA-2AEB103X" 0402L#2 807.6,2060.88 r180 bottom value="10 kΩ"
R39 "ERJ-1GN0R00C" 0201 719.02,2075.19 r90 bottom value="0 Ω"
R40 "ERJ-2RKF1000X" 0402L#2 758.39,2080.57 r270 bottom value="100 Ω"
R41 "ERJ-2GEJ100X" 0402L#2 390.32,2109.22 r180 top value="10 Ω"
R42 "ERJ-6GEY0R00V" 0805L 189.11,2024.59 r0 bottom value="0 Ω"
R43 "ERJ-2GEJ100X" 0402L#2 349.84,2254.74 r0 top value="10 Ω"
R44 "ERJ-2GEJ100X" 0402L#2 349.84,2220.25 r0 top value="10 Ω"
R45 "ERJ-2GEJ222X" 0402L#2 340,2030.31 r90 bottom value="2.2 kΩ"
R46 "ERJ-2RKF1202X" 0402L#2 512,2238.3 r90 bottom value="12 kΩ"
R47 "ERA-2AEB103X" 0402L#2 596.22,2506.98 r90 bottom value="10 kΩ"
R48 "ERA-2AEB103X" 0402L#2 689.97,2387.5 r0 bottom value="10 kΩ"
R49 "ERA-2AEB103X" 0402L#2 561.54,2506.98 r90 bottom value="10 kΩ"
R50 "ERJ-2GEJ222X" 0402L#2 626.54,2387.17 r180 bottom value="2.2 kΩ"
R51 "ERA-2AEB103X" 0402L#2 187.16,1915 r0 bottom value="10 kΩ"
R52 "ERA-2AEB103X" 0402L#2 392.95,2025.63 r90 bottom value="10 kΩ"
R53 "ERA-2AEB103X" 0402L#2 541.85,1978.01 r90 bottom value="10 kΩ"
R54 "ERA-2AEB103X" 0402L#2 581.22,1978.01 r90 bottom value="10 kΩ"
R55 "ERA-2AEB103X" 0402L#2 1094.84,2192.04 r0 top value="10 kΩ"
R56 "ERA-2AEB103X" 0402L#2 1308.42,2247.34 r180 bottom value="10 kΩ"
R57 "ERJ-2RKF1000X" 0402L#2 1337.95,2179.32 r90 bottom value="100 Ω"
R58 "ERA-2AEB103X" 0402L#2 1119.97,2243.02 r180 bottom value="10 kΩ"
R59 "ERA-2AEB103X" 0402L#2 1444.21,2305.47 r90 bottom value="10 kΩ"
R60 "ERA-2AEB103X" 0402L#2 1478.89,2300.47 r90 bottom value="10 kΩ"
R61 "ERA-2AEB103X" 0402L#2 1412.13,2318.95 r90 bottom value="10 kΩ"
R62 "ERJ-1GN0R00C" 0201 1883.16,1277.59 r270 top value="0 Ω"
R63 "ERJ-1GN0R00C" 0201 1472.13,1508.05 r0 top value="0 Ω"
R64 "ERJ-1GNF49R9C" 0201 1922.13,1244.35 r0 top value="49.9 Ω"
R65 "ERJ-1GNF1001C" 0201 2001.2,1233.32 r90 top value="1 kΩ"
R66 "ERJ-1GNF49R9C" 0201 1922.13,1221.75 r180 top value="49.9 Ω"
R67 "ERJ-1GN0R00C" 0201 1472.13,958.05 r0 top value="0 Ω"
R68 "ERJ-1GN0R00C" 0201 1883.16,1188.5 r90 top value="0 Ω"
R69 "ERJ-1GNF1300C" 0201 2917.98,902.74 r0 top value="130 Ω"
R70 "ERJ-1GNF1400C" 0201 2871.24,902.74 r180 top value="140 Ω"
R71 "ERJ-1GN0R00C" 0201 2441.25,1235.35 r180 top value="0 Ω"
R72 "ERJ-1GN0R00C" 0201 2441.25,1259.6 r180 top value="0 Ω"
R73 "ERJ-1GNF82R0C" 0201 2917.98,872.74 r180 top value="82 Ω"
R74 "ERJ-1GNF78R7C" 0201 2871.24,872.74 r0 top value="78.7 Ω"
R75 "ERA-2AEB103X" 0402L#2 3023.45,79.03 r270 bottom value="10 kΩ"
R76 "ERJ-1GN0R00C" 0201 2093.9,820.77 r0 top value="0 Ω"
R77 "ERJ-1GN0R00C" 0201 2104.93,854.79 r90 top value="0 Ω"
R78 "ERJ-1GNF33R0C" 0201 2076.93,983.24 r90 top value="33 Ω"
R79 "ERJ-1GNF10R0C" 0201 2127.15,1053.29 r90 top value="10 Ω"
R80 "ERJ-1GN0R00C" 0201 2104.93,983.24 r90 top value="0 Ω"
R81 "ERJ-1GNF24R9C" 0201 2115.95,1017.26 r180 top value="24.9 Ω"
R82 "ERJ-1GNF24R9C" 0201 2160.94,1017.26 r180 top value="24.9 Ω"
R83 "ERJ-1GN0R00C" 0201 2171.97,983.24 r90 top value="0 Ω"
R84 "ERJ-1GN0R00C" 0201 2183.98,820.77 r180 top value="0 Ω"
R85 "ERJ-1GN0R00C" 0201 2172.95,854.79 r90 top value="0 Ω"
R86 "ERJ-1GNF33R0C" 0201 2199.97,983.24 r90 top value="33 Ω"
R87 "ERJ-1GNF10R0C" 0201 2149.75,1053.29 r90 top value="10 Ω"
R88 "ERJ-1GN0R00C" 0201 2182.99,1676.83 r180 top value="0 Ω"
R89 "ERJ-1GN0R00C" 0201 2171.97,1642.8 r270 top value="0 Ω"
R90 "ERJ-1GNF33R0C" 0201 2199.97,1514.36 r270 top value="33 Ω"
R91 "ERJ-1GNF10R0C" 0201 2149.75,1444.31 r270 top value="10 Ω"
R92 "ERJ-1GN0R00C" 0201 2171.97,1514.36 r270 top value="0 Ω"
R93 "ERJ-1GNF24R9C" 0201 2160.94,1478.94 r0 top value="24.9 Ω"
R94 "ERJ-1GNF24R9C" 0201 2115.95,1478.94 r0 top value="24.9 Ω"
R95 "ERJ-1GN0R00C" 0201 2104.93,1514.36 r270 top value="0 Ω"
R96 "ERJ-1GN0R00C" 0201 2093.9,1676.83 r0 top value="0 Ω"
R97 "ERJ-1GN0R00C" 0201 2104.93,1642.8 r270 top value="0 Ω"
R98 "ERJ-1GNF33R0C" 0201 2076.93,1514.36 r270 top value="33 Ω"
R99 "ERJ-1GNF10R0C" 0201 2127.15,1444.31 r270 top value="10 Ω"
R100 "ERJ-6GEY0R00V" 0805L 2910,1510 r180 top value="0 Ω"
R101 "ERJ-6GEY0R00V" 0805L 2909.53,1440 r180 top value="0 Ω"
R102 "ERJ-6GEY0R00V" 0805L 2909.53,1370 r180 top value="0 Ω"
R103 "ERJ-1GNF1000C" 0201 2335.18,1247.47 r270 top value="100 Ω"
R104 "ERJ-1GN0R00C" 0201 2389.2,1258.8 r0 top value="0 Ω"
R105 "ERJ-1GN0R00C" 0201 2389.2,1236.15 r0 top value="0 Ω"
R106 "ERA-2AEB103X" 0402L#2 2610.97,1908.56 r270 bottom value="10 kΩ"
R107 "ERJ-1GN0R00C" 0201 2326.2,1212.85 r0 top value="0 Ω"
R108 "ERJ-1GN0R00C" 0201 2326.2,1190.25 r0 top value="0 Ω"
R109 "ERJ-1GN0R00C" 0201 2326.2,1284.74 r0 top value="0 Ω"
R110 "ERJ-1GN0R00C" 0201 2326.2,1307.34 r0 top value="0 Ω"
R111 "ERA-2AEB103X" 0402L#2 2722.25,2008.56 r90 bottom value="10 kΩ"
R112 "ERJ-1GN0R00C" 0201 2283.96,1103.29 r270 top value="0 Ω"
R113 "ERJ-1GN0R00C" 0201 2261.36,1103.29 r270 top value="0 Ω"
R114 "ERJ-1GN0R00C" 0201 2238.76,1103.29 r270 top value="0 Ω"
R115 "ERJ-1GN0R00C" 0201 2216.16,1103.29 r270 top value="0 Ω"
R116 "ERJ-1GN0R00C" 0201 2283.96,1394.31 r90 top value="0 Ω"
R117 "ERJ-1GN0R00C" 0201 2261.36,1394.31 r90 top value="0 Ω"
R118 "ERJ-1GN0R00C" 0201 2238.76,1394.31 r90 top value="0 Ω"
R119 "ERJ-1GN0R00C" 0201 2216.16,1394.31 r90 top value="0 Ω"
R120 "ERJ-1GN0R00C" 0201 2030.18,1319.66 r0 bottom value="0 Ω"
R121 "ERJ-1GN0R00C" 0201 2021.2,1125.91 r90 bottom value="0 Ω"
R122 "ERJ-2GEJ104X" 0402L#2 1496.21,691.02 r270 bottom value="100 kΩ"
R123 "ERJ-U020R00X" 0402L#2 1526.21,691.02 r270 bottom value="0 Ω"
R124 "ERA-2AEB103X" 0402L#2 1586.78,334.78 r180 bottom value="10 kΩ"
R125 "ERJ-2GEJ104X" 0402L#2 1638.32,691.12 r90 bottom value="100 kΩ"
R126 "ERJ-1GN0R00C" 0201 2193.56,1394.31 r270 top value="0 Ω"
R127 "ERJ-1GN0R00C" 0201 2071.2,1155.91 r90 bottom value="0 Ω"
R128 "ERJ-U020R00X" 0402L#2 1601.01,691.02 r270 bottom value="0 Ω"
R129 "ERJ-1GN0R00C" 0201 2193.56,1103.29 r90 top value="0 Ω"
R130 "ERJ-1GNF4991C" 0201 1691.92,1705.73 r315 bottom value="4.99 kΩ"
R131 "ERA-2AEB103X" 0402L#2 1872.7,1660.95 r135 bottom value="10 kΩ"
R132 "ERJ-1GNF3001C" 0201 2083.75,1374.15 r180 bottom value="3 kΩ"
R133 "ERJ-1GNF2491C" 0201 1727.28,1741.09 r135 bottom value="2.49 kΩ"
R134 "ERJ-1GNJ103C" 0201 3365.08,219.99 r180 top value="10 kΩ"
R135 "ERJ-1GNJ103C" 0201 3365.08,244.68 r180 top value="10 kΩ"
R136 "ERJ-1GNJ103C" 0201 3365.08,269.36 r180 top value="10 kΩ"
R137 "ERJ-1GNF2200C" 0201 3737.11,383.27 r0 top value="220 Ω"
R138 "ERJ-1GN0R00C" 0201 3611.42,2360 r0 top value="0 Ω"
R139 "ERJ-1GN0R00C" 0201 3661.42,858.96 r90 top value="0 Ω"
R140 "ERJ-1GN0R00C" 0201 3702.65,874.5 r45 top value="0 Ω"
R141 "ERJ-1GN0R00C" 0201 3702.65,824.5 r45 top value="0 Ω"
R142 "ERJ-1GN0R00C" 0201 3323.98,1305 r0 top value="0 Ω"
R143 "ERJ-1GN0R00C" 0201 3523.92,970.77 r135 top value="0 Ω"
R144 "ERJ-1GN0R00C" 0201 3523.92,870.77 r135 top value="0 Ω"
R145 "ERJ-1GN0R00C" 0201 3523.92,820.77 r135 top value="0 Ω"
R146 "ERJ-2RKF1000X" 0402L#2 3461.42,2258.27 r90 top value="100 Ω"
R147 "ERA-2AEB103X" 0402L#2 1133.18,2419.8 r90 bottom value="10 kΩ"
R148 "ERA-2AEB103X" 0402L#2 1015.23,2290.74 r0 bottom value="10 kΩ"
R149 "ERJ-2RKF1000X" 0402L#2 1034.92,2345.43 r270 bottom value="100 Ω"
R150 "ERA-2AEB103X" 0402L#2 1054.6,2290.74 r0 bottom value="10 kΩ"
R151 "ERJ-1GN0R00C" 0201 3523.92,720.77 r135 top value="0 Ω"
SH-J1 "SPC02SYAN" SPC02SYAN 2675,1740 r90 top value=1x2
SH-J2 "HMSC-G" HMSC-G 2005,1425 r135 top value=1x2
SW1 "500ASSP1M2QE" 500ASSP1M2QE 1088.81,298.32 r270 top
SW2 "cmp00353" 450301014042 107.48,1815 r270 top
SW3 "cmp00353" 450301014042 2848.45,98.72 r180 top
SW4 "FSMSM" FSMSM 1563.61,529.61 r90 top
SW5 "CHS-02TA" CHS-02TA 1742.52,1690.49 r45 top
T1 "ADT1-1WT+" CD542 1681.11,1233.05 r0 top
T2 "ADT1-6T+" CD637 2138.45,618.72 r0 top
T3 "ADT1-6T+" CD637 2137.46,1878.88 r180 top
TP1 "5010" Keystone5010 786.05,648 r0 top
TP2 "5125" Keystone5125 466.33,700.79 r0 top
TP3 "5116" KEYSTONE5116 1984.19,1030.26 r90 top
U1 "ADC3664IRSB" RSB0040E 2185.69,1248.8 r0 top
U2 "TPS259261DRC" DRC0010J 1201.22,353.52 r90 bottom
U3 "TPS82140SILR" SIL0008D 1052.5,682.49 r90 bottom
U4 "TPSM82913RDU" RDU0028A 169.58,991.3 r0 bottom
U5 "INA180B1IDBVR" DBV0005A 909.65,1588.15 r0 bottom
U6 "TPS7A9401DSC" DSC0010 617.53,1532.05 r0 top
U7 "INA180B1IDBVR" DBV0005A 909.65,1188.15 r0 bottom
U8 "TPS7A9401DSC" DSC0010 617.53,1132.05 r0 top
U9 "ADS1119IRTER" RTE0016D 1278.89,1948.29 r180 bottom
U10 "SN74LVC2G125DCUT" DCU0008A 728.86,2203.24 r270 bottom
U11 "FT4232HL-REEL" LQFP64-MFG 689.49,2217.81 r0 top locked
U12 "93LC46B-I/ST" TSSOP-8 595,2221.75 r270 bottom
U13 "TMUX1136DGS" DQA0010A 1245.41,2323.6 r0 bottom
U14 "SN74AVC4T774BQB" BQB0016A-MFG 1054.25,2162.51 r0 bottom
U15 "SN74CBTLV3257RSV" RSV0016A 1226.77,2162.51 r90 bottom
U16 "SN74LVC1G125DRL" DRL0005A 1330.31,2095.1 r90 bottom
U17 "TMUX136RSE" RSE0010A 2911.79,1124.55 r90 top
U18 "DS25BR100TSD/NOPB" NGQ0008A 2892.11,992.86 r90 top
U19 "TPS3125J18DBVR" DBV0005A 1563.61,576.69 r270 bottom
U20 "SN74AUP1G08DCKT" DCK0005A 1563.61,408.64 r0 bottom
U21 "REF35160QDBV" DBV0006A 1926.24,1554.52 r315 bottom
U22 "24LC64FT-I/MNY" TDFN8 3260,254.52 r180 top
U23 "SN74LVC1G125DRL" DRL0005A 1064.05,2419.8 r180 bottom
Y1 "ABM3-12.000MHZ-D2Y-T" XTAL_ABM3 403.18,2522.22 r45 top
ZZ1 "These assemblies are ESD sensitive, ESD precautions shall be observed." AssemblyNote 85,2970 r0 top

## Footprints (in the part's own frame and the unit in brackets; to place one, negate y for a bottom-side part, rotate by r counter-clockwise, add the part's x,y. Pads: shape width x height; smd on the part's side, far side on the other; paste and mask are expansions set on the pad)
0201 [mm] "Data from Kemet datasheet CC101_COM dated 7/28/11"
  rrect20% 0.36x0.32 smd mask+0.051: 1(-0.28,0) 2(0.28,0)
  body extent -0.31,-0.16 0.31,0.16, height 0.26
0201_cap [mm] "Data from Kemet datasheet CC101_COM dated 7/28/11"
  rrect20% 0.36x0.32 smd mask+0.051: 1(-0.28,0) 2(0.28,0)
  body extent -0.31,-0.16 0.31,0.16, height 0.26
0402L#1 [mm] "0402 from SM-752 data"
  rect 0.6x0.5 smd: 1(-0.5,0) 2(0.5,0)
  body extent -0.55,-0.3 0.55,0.3, height 0.6
0402L#2 [mm] "0402 from SM-752 data"
  rrect20% 0.6x0.5 smd mask+0.051: 1(-0.5,0) 2(0.5,0)
  body extent -0.55,-0.3 0.55,0.3, height 0.6
0402L_cap#1 [mm] "0402 from SM-752 data"
  rrect20% 0.6x0.5 smd mask+0.051: 1(-0.5,0) 2(0.5,0)
  body extent -0.55,-0.3 0.55,0.3, height 0.6
0402L_cap#2 [mm] "0402 from SM-752 data"
  rect 0.6x0.5 smd: 1(-0.5,0) 2(0.5,0)
  body extent -0.55,-0.3 0.55,0.3, height 0.6
500ASSP1M2QE [mm]
  rect 1.635x1.635 hole 1.09: 1(-2.54,0)
  round 1.635 hole 1.09: 2(0,0) 3(2.54,0)
  silkscreen extent -5.08,-2.54 5.08,2.54, body extent -5.08,-2.54 5.08,2.54, height 13.32
0603L [mm] "0603 from SM-752 data"
  rrect20% 0.8x0.85 smd: 1(-0.7,0) 2(0.7,0)
  silkscreen extent -0.07,-0.33 0.07,0.33, body extent -0.87,-0.47 0.87,0.47, height 1
0603L_cap [mm] "0603 from SM-752 data"
  rrect20% 0.8x0.85 smd: 1(-0.7,0) 2(0.7,0)
  silkscreen extent -0.07,-0.33 0.07,0.33, body extent -0.87,-0.47 0.87,0.47, height 1
0805L [mm] "0805 from SM-752 data"
  rrect20% 1.1x1.4 smd: 1(-0.75,0) 2(0.75,0)
  body extent -1,-0.62 1,0.63, height 0.7
0805L_cap [mm] "0805 from SM-752 data"
  rrect20% 1.1x1.4 smd: 1(-0.75,0) 2(0.75,0)
  body extent -1.1,-0.72 1.1,0.72, height 1.45
450301014042 [mm]
  round 1.65 hole 1.016: 1(0,0) 2(-2.54,0)
  rect 1.65x1.65 hole 1.016: 3(2.54,0)
  silkscreen extent -4.25,-1.3 4.25,1.3, body extent -4.98,-1.25 5.02,1.25, height 5.9
AssemblyNote [mil] "Assembly Note"
BQB0016A-MFG [mm]
  rrect42% 0.24x0.6 smd paste+0 mask+0.07: 1(-0.25,1.65) 8(-0.25,-1.65) 9(0.25,-1.65) 16(0.25,1.65)
  rrect42% 0.6x0.24 smd paste+0 mask+0.07: 2(-1.15,1.25) 3(-1.15,0.75) 4(-1.15,0.25) 5(-1.15,-0.25) 6(-1.15,-0.75) 7(-1.15,-1.25) 10(1.15,-1.25) 11(1.15,-0.75) 12(1.15,-0.25) 13(1.15,0.25) 14(1.15,0.75) 15(1.15,1.25)
  round 0.454 hole 0.2 mask+0.05: 17(0,-0.75) 17(0,0.75)
  rrect10% 1x2 smd paste-1000 mask+0.07: 17(0,0)
  silkscreen extent -1.67,-1.8 1.3,1.8, body extent -1.25,-1.75 1.25,1.75, height 0.8
cbts130a [mm]
  round 5.5 hole 3.4 paste-2539.97 mask+0: ""(0,0)
  body extent -3.18,-2.75 3.18,2.75, height 2.09
CCS0603FLxLxx [mm]
  rrect33% 1.41x0.92 smd: 1(-0.9,0) 2(0.89,0)
  body extent -0.93,-0.52 0.93,0.52, height 0.66
CD542 [mil]
  rrect6% 100x65 smd paste+0 mask+2.76: 1(-100,100) 2(-100,0) 3(-100,-100) 4(100,-100) 5(100,0) 6(100,100)
  silkscreen extent -183,-158 112,158, body extent -154,-161 154,161, height 10
CD637 [mil]
  rrect6% 65x100 smd paste+0 mask+0: 1(-100,-100) 2(0,-100) 3(100,-100) 4(100,100) 5(0,100) 6(-100,100)
  silkscreen extent -158,-184 158,112, body extent -161,-154 161,154, height 10
CE_Mark_5mm [mil] "Minimum text height for CE Mark"
  silkscreen extent -138,-98 138,98
CHS-02TA [mm]
  rrect50% 0.76x1.6 smd mask+0.07: 1(-0.635,2.54) 2(0.635,2.54) 3(0.635,-2.54) 4(-0.635,-2.54)
  silkscreen extent -1.47,2.73 -1.33,2.87, body extent -2.03,-2.8 2.03,2.8, height 2.5
DBV0005A [mm] "SOT23, 5-Leads, Body 2.9x1.6mm, Pitch 0.95mm, Lead Span 2.8mm, IPC High Density"
  rrect18% 1.1x0.6 smd mask+0.07: 1(-1.3,0.95) 2(-1.3,0) 3(-1.3,-0.95) 4(1.3,-0.95) 5(1.3,0.95)
  silkscreen extent -0.35,-1.55 0.35,1.55, body extent -1.42,-1.46 1.42,1.46, height 1.09
DBV0006A [mm] "SOT23, 6-Leads, Body 2.9x1.6mm, Pitch 0.95mm, Lead Span 2.8mm, IPC High Density"
  rrect18% 1.1x0.6 smd mask+0.07: 1(-1.3,0.95) 2(-1.3,0) 3(-1.3,-0.95) 4(1.3,-0.95) 5(1.3,0) 6(1.3,0.95)
  silkscreen extent -0.35,-1.55 0.35,1.55, body extent -1.5,-1.5 1.5,1.5, height 1.3
DCK0005A [mm] "SOT353, 5-Leads, Body 2x1.3mm, Pitch 0.65mm, Lead Span 2.1mm, IPC High Density"
  rrect25% 0.9x0.4 smd mask+0.05: 1(-1.1,0.65) 2(-1.1,0) 3(-1.1,-0.65) 4(1.1,-0.65) 5(1.1,0.65)
  silkscreen extent -0.25,-1.1 0.25,1.1, body extent -1.14,-1 1.14,1, height 0.95
DCU0008A [mm] "TSSOP, 8-Leads, Body 2x2.3mm, Pitch 0.5mm, IPC High Density"
  rrect30% 0.8x0.3 smd mask+0.05: 1(-1.55,0.75) 2(-1.55,0.25) 3(-1.55,-0.25) 4(-1.55,-0.75) 5(1.55,-0.75) 6(1.55,-0.25) 7(1.55,0.25) 8(1.55,0.75)
  silkscreen extent -1.05,-1.05 0.38,1.05, body extent -1.56,-1 1.56,1, height 0.9
DQA0010A [mm] "SON, 10-Leads, Body 1x2.5mm, Pitch 0.5mm, TI Recommended"
  rrect50% 0.565x0.2 smd mask+0.07: 1(-0.417,1) 2(-0.417,0.5) 4(-0.417,-0.5) 5(-0.417,-1) 6(0.417,-1) 7(0.417,-0.5) 9(0.417,0.5) 10(0.417,1)
  rrect28% 0.565x0.36 on Bottom Paste mask+0.07: 3(-0.417,0) 8(0.417,0)
  rrect25% 0.565x0.4 smd paste-0.2 mask+0.07: 3(-0.417,0) 8(0.417,0)
  silkscreen extent -0.67,-1.45 0.55,1.45, body extent -0.5,-1.25 0.5,1.25, height 0.55
DQK0006C [mm] "WSON"
  rrect12% 0.9x0.86 on Bottom Paste: 0(0,0.325)
  rrect34% 0.7x0.29 on Bottom Paste: 0(0.095,-0.65)
  rrect33% 0.45x0.3 smd: 1(-0.975,0.65) 2(-0.975,0) 3(-0.975,-0.65) 4(0.975,-0.65) 5(0.975,0) 6(0.975,0.65)
  rrect33% 0.75x0.3 smd paste-0.15: 7(0.095,-0.65)
  rrect11% 1x0.95 smd paste-0.5: 8(0,0.325)
  silkscreen extent -1.15,-1.15 1.15,1.15, body extent -1,-1 1,1, height 0.75
DRC0010J [mm] "VSON-10"
  rrect42% 0.6x0.24 smd mask+0.07: 1(-1.4,1) 2(-1.4,0.5) 3(-1.4,0) 4(-1.4,-0.5) 5(-1.4,-1) 6(1.4,-1) 7(1.4,-0.5) 8(1.4,0) 9(1.4,0.5) 10(1.4,1)
  round 0.454 hole 0.2 mask+0.05: 11(-0.575,0) 11(0,-0.95) 11(0,0.95) 11(0.575,0)
  round 0.025 smd mask+0.07: 11(0,0)
  Top Layer region: -0.375,-1.65 -0.375,-1.2 -0.775,-1.2 -0.794,-1.196 -0.81,-1.185 -0.821,-1.169 -0.825,-1.15 -0.825,-1.15 -0.825,1.15 -0.821,1.169 -0.81,1.185 -0.794,1.196 -0.775,1.2 -0.775,1.2 -0.375,1.2 -0.375,1.65 -0.371,1.669 -0.36,1.685 -0.344,1.696 -0.325,1.7 -0.325,1.7 -0.325,1.7 -0.175,1.7 -0.175,1.7 -0.156,1.696 -0.14,1.685 -0.129,1.669 -0.125,1.65 -0.125,1.65 -0.125,1.2 0.125,1.2 0.125,1.65 0.129,1.669 0.14,1.685 0.156,1.696 0.175,1.7 0.175,1.7 0.175,1.7 0.325,1.7 0.325,1.7 0.344,1.696 0.36,1.685 0.371,1.669 0.375,1.65 0.375,1.65 0.375,1.2 0.775,1.2 0.794,1.196 0.81,1.185 0.821,1.169 0.825,1.15 0.825,1.15 0.825,-1.15 0.821,-1.169 0.81,-1.185 0.794,-1.196 0.775,-1.2 0.775,-1.2 0.375,-1.2 0.375,-1.65 0.371,-1.669 0.36,-1.685 0.344,-1.696 0.325,-1.7 0.325,-1.7 0.175,-1.7 0.156,-1.696 0.14,-1.685 0.129,-1.669 0.125,-1.65 0.125,-1.65 0.125,-1.2 -0.125,-1.2 -0.125,-1.65 -0.129,-1.669 -0.14,-1.685 -0.156,-1.696 -0.175,-1.7 -0.175,-1.7 -0.325,-1.7 -0.344,-1.696 -0.36,-1.685 -0.371,-1.669 -0.375,-1.65
  silkscreen extent -1.97,0.95 -1.84,1.08, body extent -1.5,-1.5 1.5,1.5, height 1
DRL0005A [mm] "SOTFL, 5-Flat Leads, Body 1.2x1.6x0.6mm, Pitch 0.5mm, TI recommended"
  rrect33% 0.67x0.3 smd mask+0.05: 1(-0.74,0.5) 2(-0.74,0) 3(-0.74,-0.5) 4(0.74,-0.5) 5(0.74,0.5)
  silkscreen extent -0.9,-0.95 0.5,0.95, body extent -0.8,-0.8 0.8,0.8, height 0.6
DSC0010 [mm]
  rrect50% 0.6x0.24 smd paste+0 mask+0.07: 1(-1.4,1) 2(-1.4,0.5) 3(-1.4,0) 4(-1.4,-0.5) 5(-1.4,-1) 6(1.4,-1) 7(1.4,-0.5) 8(1.4,0) 9(1.4,0.5) 10(1.4,1)
  round 0.454 hole 0.2 mask+0.05: 11(-0.575,0) 11(0,-0.95) 11(0,0.95) 11(0.575,0)
  rrect6% 1.65x2.4 smd paste-1000 mask+0: 11(0,0)
  silkscreen extent -1.58,-1.55 1.55,1.88, body extent -1.8,-1.8 1.8,1.8, height 0.25
ESD_Overlay_Small [mil]
  silkscreen extent -62,-48 64,61
FCC_disclaimer [mil]
FDL_Small [mil]
  silkscreen extent -54,-32 54,73
Fiducial10-20 [mm]
  round 1 smd paste-0.508 mask+0.203: 1(0,0)
FIL_BNX002-11 [mm]
  rect 1.8x1.8 hole 1.2: 1(2.5,2.5)
  round 1.8 hole 1.2: 2(2.5,-2.5) 3(-2.5,2.5) 4(-2.5,-2.5) 4(0,0) 4(5,0)
  silkscreen extent -6,-5.5 6,6.35, body extent -6,-5.5 6,5.5, height 13
FP-132134-15_CONN_SMA_JACK-MFG [mm]
  round 0.864 smd paste+0 mask+0: 1(0,0)
  round 2.6 hole 1.7 paste-2539.97 mask+0: 2(-2.54,2.54) 3(2.54,2.54) 4(-2.54,-2.54) 5(2.54,-2.54)
  silkscreen extent -3.6,-3.6 3.6,3.6, body extent -3.94,-3.94 3.94,3.94, height 0.25
FP-USB4105-GF-A_CONN_USB_9MM58_7MM53-MFG [mm]
  rrect100% 1x2.1 hole 1.7 slot 0.6 at 0 deg paste-2539.97 mask+0: 1(-4.32,3.015) 2(4.32,3.015)
  rrect100% 1x1.8 hole 1.4 slot 0.6 at 0 deg paste-2539.97 mask+0: 3(-4.32,-1.165) 4(4.32,-1.165)
  rrect17% 0.6x1.15 smd paste+0 mask+0: A1(-3.2,3.59) A4(-2.4,3.59) B1(3.2,3.59) B4(2.4,3.59)
  rrect33% 0.3x1.15 smd paste+0 mask+0: A5(-1.25,3.59) A6(-0.25,3.59) A7(0.25,3.59) A8(1.25,3.59) B5(1.75,3.59) B6(0.75,3.59) B7(-0.75,3.59) B8(-1.75,3.59)
  round 0.65 hole 0.65 unplated paste-2539.97 mask+0: ""(-2.89,2.515) ""(2.89,2.515)
  silkscreen extent -4.86,0.11 4.86,4.84, body extent -4.96,-3.94 4.96,4.27, height 0.25
FSMSM [mm]
  rrect10% 2.2x1.6 smd: 1(-4.6,0) 2(4.6,0)
  body extent -5.54,-1.75 5.54,1.75, height 4.2
HDR_2x1_TH_VT_50mil [mil] "Sullins"
  rrect10% 41x41 hole 28: 1(-25,0)
  round 41 hole 28: 2(25,0)
  silkscreen extent -50,-42 50,53, body extent -50,-42 50,42, height 157
HMSC-G [mil]
  body extent -49,-30 49,30, height 160
IND_LQG15H [mm] "MuRata"
  rrect20% 0.55x0.6 smd mask+0.07: 1(-0.475,0) 2(0.475,0)
  body extent -0.52,-0.27 0.52,0.27, height 0.55
Keystone5010 [mil] "Keystone Multipurpose loops"
  round 87 hole 63: 1(0,0)
  silkscreen extent -70,-70 70,70, body extent -63,-63 63,62, height 319
KEYSTONE5116 [mil] "For Keystone 500x miniature loop terminals"
  round 80 hole 40: 1(0,0)
  silkscreen extent -58,-58 58,58, body extent -50,-49 50,51, height 183
Keystone5125 [mil] "Keystone Multipurpose loops"
  round 87 hole 63: 1(0,0)
  silkscreen extent -70,-70 70,70, body extent -63,-63 63,62, height 319
Label_650x200 [mil] "Thermal Transfer Label"
  silkscreen extent -325,-100 325,100
LED_LTST-C190-Green [mm] "Lite-On"
  rect 0.8x0.8 smd: 1(-0.75,0) 2(0.75,0)
  silkscreen extent -1.1,-0.8 1.8,0.8, body extent -0.85,-0.45 0.85,0.45, height 0.91
LQFP64-MFG [mm]
  rrect33% 1.65x0.3 smd paste+0 mask+0.05: 1(-5.575,3.75)
  rrect100% 1.65x0.3 smd paste+0 mask+0.05: 2(-5.575,3.25) 3(-5.575,2.75) 4(-5.575,2.25) 5(-5.575,1.75) 6(-5.575,1.25) 7(-5.575,0.75) 8(-5.575,0.25) 9(-5.575,-0.25) 10(-5.575,-0.75) 11(-5.575,-1.25) 12(-5.575,-1.75) 13(-5.575,-2.25) 14(-5.575,-2.75) 15(-5.575,-3.25) 16(-5.575,-3.75) 33(5.575,-3.75) 34(5.575,-3.25) 35(5.575,-2.75) 36(5.575,-2.25) 37(5.575,-1.75) 38(5.575,-1.25) 39(5.575,-0.75) 40(5.575,-0.25) 41(5.575,0.25) 42(5.575,0.75) 43(5.575,1.25) 44(5.575,1.75) 45(5.575,2.25) 46(5.575,2.75) 47(5.575,3.25) 48(5.575,3.75)
  rrect100% 0.3x1.65 smd paste+0 mask+0.05: 17(-3.75,-5.575) 18(-3.25,-5.575) 19(-2.75,-5.575) 20(-2.25,-5.575) 21(-1.75,-5.575) 22(-1.25,-5.575) 23(-0.75,-5.575) 24(-0.25,-5.575) 25(0.25,-5.575) 26(0.75,-5.575) 27(1.25,-5.575) 28(1.75,-5.575) 29(2.25,-5.575) 30(2.75,-5.575) 31(3.25,-5.575) 32(3.75,-5.575) 49(3.75,5.575) 50(3.25,5.575) 51(2.75,5.575) 52(2.25,5.575) 53(1.75,5.575) 54(1.25,5.575) 55(0.75,5.575) 56(0.25,5.575) 57(-0.25,5.575) 58(-0.75,5.575) 59(-1.25,5.575) 60(-1.75,5.575) 61(-2.25,5.575) 62(-2.75,5.575) 63(-3.25,5.575) 64(-3.75,5.575)
  silkscreen extent -7.12,-5.05 5.05,5.05, body extent -6.5,-6.5 6.5,6.5, height 0.25
NGQ0008A [mm] "WSON -8"
  rrect50% 0.6x0.25 smd mask+0.05: 1(-1.4,0.75) 2(-1.4,0.25) 3(-1.4,-0.25) 4(-1.4,-0.75) 5(1.4,-0.75) 6(1.4,-0.25) 7(1.4,0.25) 8(1.4,0.75)
  round 0.35 hole 0.2 mask+0.05: 9(0,0.75) 9(0,0) 9(0,-0.75)
  rrect12% 1.6x2 smd mask+0.05: 9(0,0)
  silkscreen extent -2.05,1.2 -1.95,1.3, body extent -1.51,-1.5 1.51,1.5, height 0.75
